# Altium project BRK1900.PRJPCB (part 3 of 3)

## Sheet Ethernet.SchDoc: BRK1900 - Ethernet
size C; Organization: Opal Kelly; Address1: 13500 SW 72nd Ave STE 100; Address2: Portland, OR  97223; Address3: 217.391.3724; Address4: http://www.opalkelly.com; DocumentNumber: 8; Revision: 1; SheetNumber: 8; SheetTotal: 11; PageSetup: Record=PageOptions¦CenterHorizontal=True¦CenterVertical=True¦PrintScale=0.52¦XCorrection=1.00¦YCorrection=1.00¦PrintKind=0¦BorderSize=5000000¦LeftOffset=0¦BottomOffset=0¦Orientation=2¦PaperLength=1000¦PaperWidth=1000¦Scale=100¦PaperSource=7¦PrintQuality=-4¦MediaType=1¦DitherType=10¦PaperKind=Letter¦PrintScaleMode=1
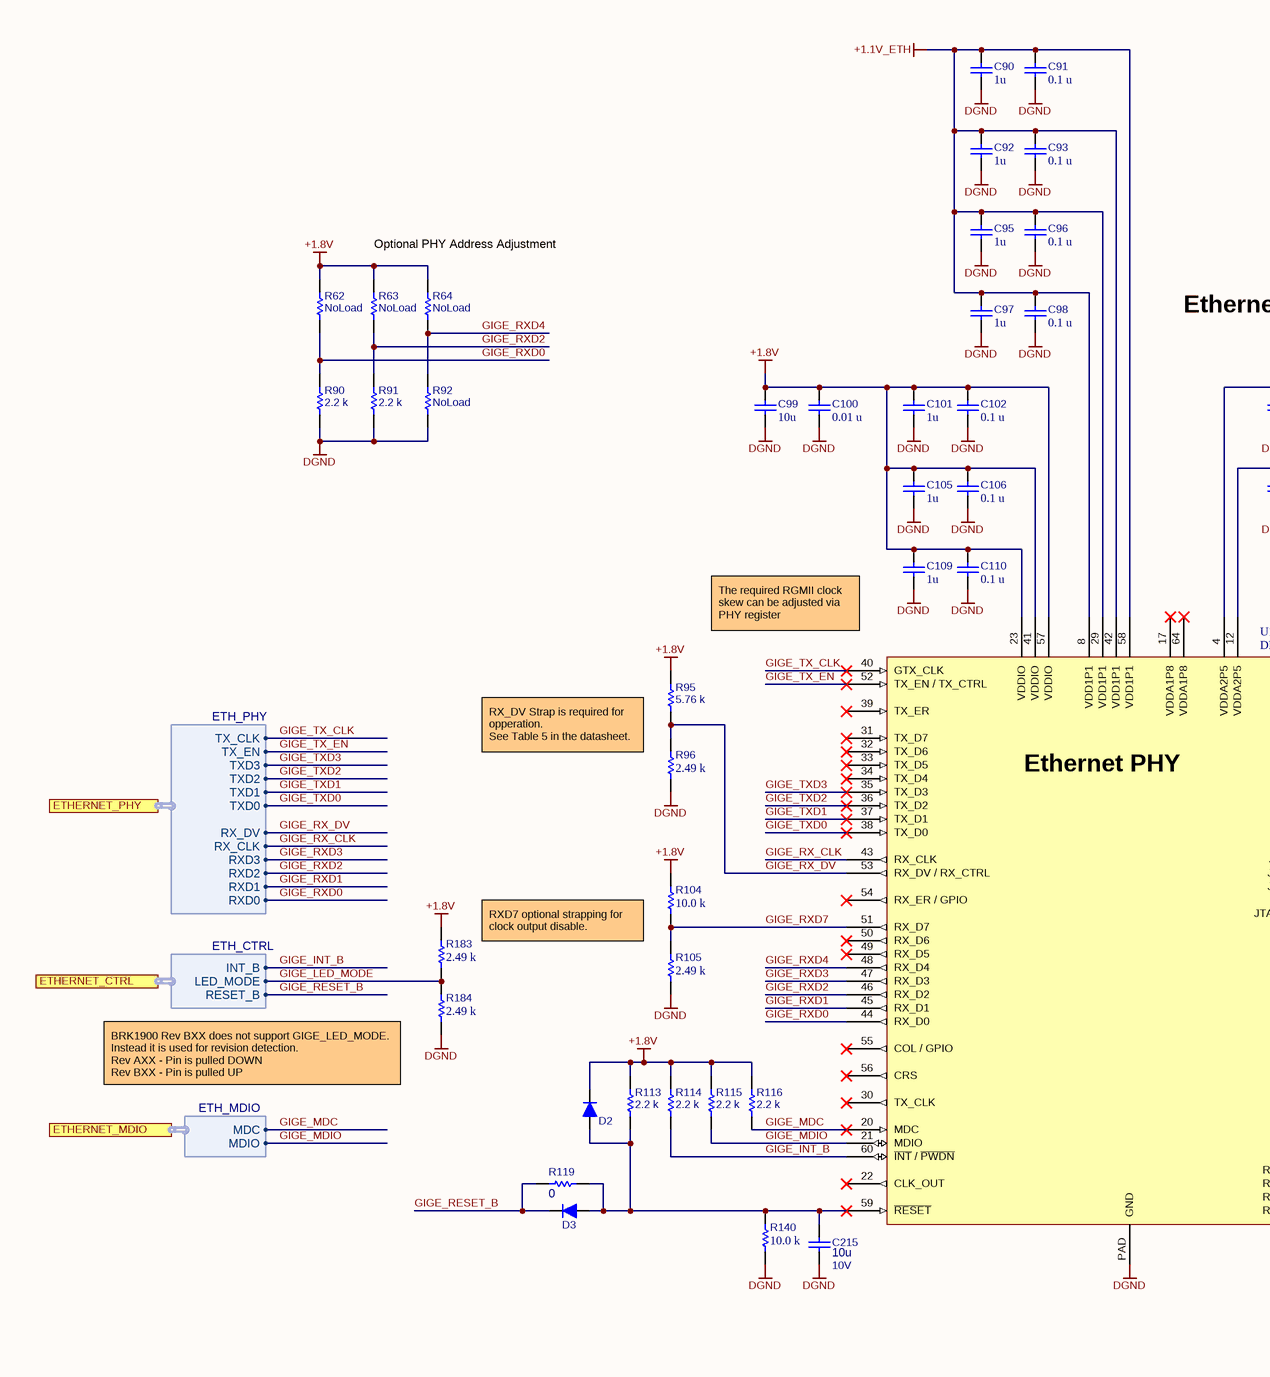
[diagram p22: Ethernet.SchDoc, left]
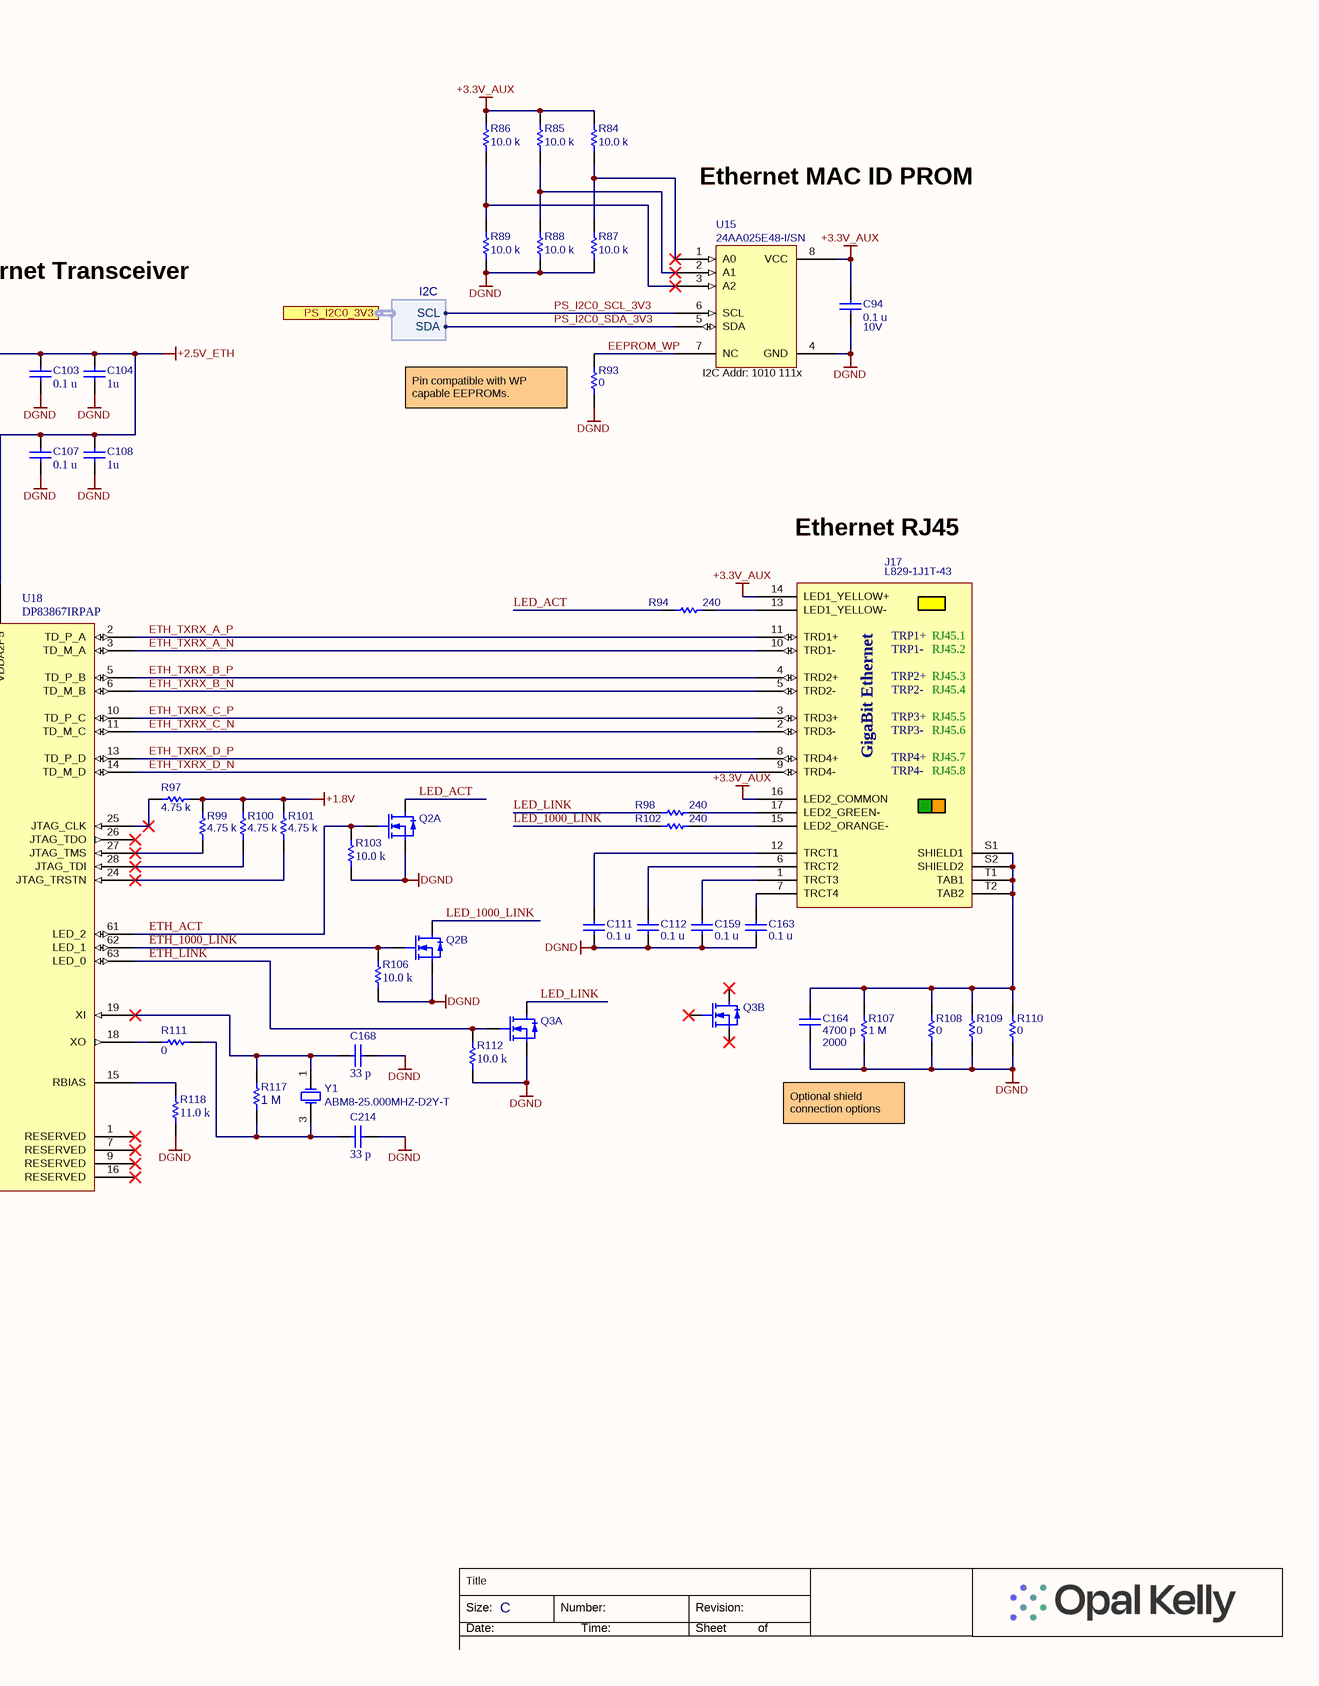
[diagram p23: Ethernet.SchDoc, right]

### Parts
C90  value 1u  [CAPC1005X06A]  (hidden comment: LMK105BJ105KV-F)
C91  value 0.1 u  [CAPC1005X06A]  (hidden comment: C0402C104K8PACTU)
C92  value 1u  [CAPC1005X06A]  (hidden comment: LMK105BJ105KV-F)
C93  value 0.1 u  [CAPC1005X06A]  (hidden comment: C0402C104K8PACTU)
C94  value 0.1 u  Voltage: 10V  [CAPC1005X06A]  (hidden comment: C0402C104K8PACTU)
C95  value 1u  [CAPC1005X06A]  (hidden comment: LMK105BJ105KV-F)
C96  value 0.1 u  [CAPC1005X06A]  (hidden comment: C0402C104K8PACTU)
C97  value 1u  [CAPC1005X06A]  (hidden comment: LMK105BJ105KV-F)
C98  value 0.1 u  [CAPC1005X06A]  (hidden comment: C0402C104K8PACTU)
C99  value 10u  [CAPC2012X14N]  (hidden comment: EMK212BJ106KG-T)
C100  value 0.01 u  [CAPC1005X06A]  (hidden comment: C0402C103K4RACTU)
C101  value 1u  [CAPC1005X06A]  (hidden comment: LMK105BJ105KV-F)
C102  value 0.1 u  [CAPC1005X06A]  (hidden comment: C0402C104K8PACTU)
C103  value 0.1 u  [CAPC1005X06A]  (hidden comment: C0402C104K8PACTU)
C104  value 1u  [CAPC1005X06A]  (hidden comment: LMK105BJ105KV-F)
C105  value 1u  [CAPC1005X06A]  (hidden comment: LMK105BJ105KV-F)
C106  value 0.1 u  [CAPC1005X06A]  (hidden comment: C0402C104K8PACTU)
C107  value 0.1 u  [CAPC1005X06A]  (hidden comment: C0402C104K8PACTU)
C108  value 1u  [CAPC1005X06A]  (hidden comment: LMK105BJ105KV-F)
C109  value 1u  [CAPC1005X06A]  (hidden comment: LMK105BJ105KV-F)
C110  value 0.1 u  [CAPC1005X06A]  (hidden comment: C0402C104K8PACTU)
C111  value 0.1 u  [CAPC1005X06A]  (hidden comment: TMK105BJ104KV-F)
C112  value 0.1 u  [CAPC1005X06A]  (hidden comment: TMK105BJ104KV-F)
C159  value 0.1 u  [CAPC1005X06A]  (hidden comment: TMK105BJ104KV-F)
C163  value 0.1 u  [CAPC1005X06A]  (hidden comment: TMK105BJ104KV-F)
C164  value 4700 p  Voltage: 2000  [CC4532-1812]  (hidden comment: GR443DR73D472KW01L)
C168  value 33 p  [CAPC1005X06A]  (hidden comment: C0402C330J5GACTU)
C214  value 33 p  [CAPC1005X06A]  (hidden comment: C0402C330J5GACTU)
C215  value 10u  Voltage: 10V  [CAPC2012X14N]  (hidden comment: LMK212BJ106KG-T)
D2  Diode  [SOD-123]  (value not drawn)
D3  Diode  [SOD-123]  (value not drawn)
J17  L829-1J1T-43  [L829-1J1T-43]
Q2  SI1922EDH-T1-GE3  [SOT363-6N]  (value not drawn)  (parts A,B of 2)
Q3  SI1922EDH-T1-GE3  [SOT363-6N]  (value not drawn)  (parts A,B of 2)
R62  NoLoad  [RESC1005X06A]
R63  NoLoad  [RESC1005X06A]
R64  NoLoad  [RESC1005X06A]
R84  value 10.0 k  [RESC1005X06A]  (hidden comment: CRCW040210K0FKED)
R85  value 10.0 k  [RESC1005X06A]  (hidden comment: CRCW040210K0FKED)
R86  value 10.0 k  [RESC1005X06A]  (hidden comment: CRCW040210K0FKED)
R87  value 10.0 k  [RESC1005X06A]  (hidden comment: CRCW040210K0FKED)
R88  value 10.0 k  [RESC1005X06A]  (hidden comment: CRCW040210K0FKED)
R89  value 10.0 k  [RESC1005X06A]  (hidden comment: CRCW040210K0FKED)
R90  value 2.2 k  [RESC1005X06A]  (hidden comment: CRCW04022K20JNED)
R91  value 2.2 k  [RESC1005X06A]  (hidden comment: CRCW04022K20JNED)
R92  NoLoad  [RESC1005X06A]
R93  value 0  [RESC1005X06A]  (hidden comment: CRCW04020000Z0ED)
R94  value 240  [RESC1005X06A]  (hidden comment: CRCW0402240RFKED)
R95  value 5.76 k  [RESC1005X06A]  (hidden comment: CRCW04025K76FKEDC)
R96  value 2.49 k  [RESC1005X06A]  (hidden comment: CRCW04022K49FKED)
R97  value 4.75 k  [RESC1005X06A]  (hidden comment: CRCW04024K75FKED)
R98  value 240  [RESC1005X06A]  (hidden comment: CRCW0402240RFKED)
R99  value 4.75 k  [RESC1005X06A]  (hidden comment: CRCW04024K75FKED)
R100  value 4.75 k  [RESC1005X06A]  (hidden comment: CRCW04024K75FKED)
R101  value 4.75 k  [RESC1005X06A]  (hidden comment: CRCW04024K75FKED)
R102  value 240  [RESC1005X06A]  (hidden comment: CRCW0402240RFKED)
R103  value 10.0 k  [RESC1005X06A]  (hidden comment: CRCW040210K0FKED)
R104  value 10.0 k  [RESC1005X06A]  (hidden comment: CRCW040210K0FKED)
R105  value 2.49 k  [RESC1005X06A]  (hidden comment: CRCW04022K49FKED)
R106  value 10.0 k  [RESC1005X06A]  (hidden comment: CRCW040210K0FKED)
R107  value 1 M  [RESC1005X06A]  (hidden comment: CRCW04021M00JNED)
R108  value 0  [RESC1005X06A]  (hidden comment: CRCW04020000Z0ED)
R109  value 0  [RESC1005X06A]  (hidden comment: CRCW04020000Z0ED)
R110  value 0  [RESC1005X06A]  (hidden comment: CRCW04020000Z0ED)
R111  value 0  [RESC1005X06A]  (hidden comment: CRCW04020000Z0ED)
R112  value 10.0 k  [RESC1005X06A]  (hidden comment: CRCW040210K0FKED)
R113  value 2.2 k  [RESC1005X06A]  (hidden comment: CRCW04022K20JNED)
R114  value 2.2 k  [RESC1005X06A]  (hidden comment: CRCW04022K20JNED)
R115  value 2.2 k  [RESC1005X06A]  (hidden comment: CRCW04022K20JNED)
R116  value 2.2 k  [RESC1005X06A]  (hidden comment: CRCW04022K20JNED)
R117  value 1 M  [RESC1005X06A]  (hidden comment: CRCW04021M00JNED)
R118  value 11.0 k  [RESC1005X06A]  (hidden comment: CRCW040211K0FKED)
R119  value 0  [RESC1005X06A]  (hidden comment: CRCW04020000Z0ED)
R140  value 10.0 k  [RESC1005X06A]  (hidden comment: CRCW040210K0FKED)
R183  value 2.49 k  [RESC1005X06A]  (hidden comment: CRCW04022K49FKED)
R184  value 2.49 k  [RESC1005X06A]  (hidden comment: CRCW04022K49FKED)
U15  24AA025E48-I/SN  [SO-G8]
U18  DP83867IRPAP  [DP83867IRPAP]
Y1  ABM8-25.000MHZ-D2Y-T  [OSC_SMD_32x25]

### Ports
ETHERNET_CTRL (harness ETH_CTRL), ETHERNET_MDIO (harness ETH_MDIO), ETHERNET_PHY (harness ETH_PHY), PS_I2C0_3V3 (harness I2C)

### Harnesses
ETH_PHY: TX_CLK, TX_EN, TXD3, TXD2, TXD1, TXD0, RX_DV, RX_CLK, RXD3, RXD2, RXD1, RXD0
ETH_MDIO: MDC, MDIO
ETH_CTRL: INT_B, LED_MODE, RESET_B
I2C: SCL, SDA

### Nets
+1.1V_ETH: C90.2 C91.2 C92.2 C93.2 C95.2 C96.2 C97.2 C98.2 U18.8(VDD1P1) U18.29(VDD1P1) U18.42(VDD1P1) U18.58(VDD1P1)
+1.8V: C99.2 C100.2 C101.2 C102.2 C105.2 C106.2 C109.2 C110.2 D2.2(K) R62.2 R63.2 R64.2 R95.2 R97.1 R99.2 R100.2 R101.2 R104.2 R113.2 R114.2 R115.2 R116.2 R183.2 U18.23(VDDIO) U18.41(VDDIO) U18.57(VDDIO)
+2.5V_ETH: C103.2 C104.2 C107.2 C108.2 U18.4(VDDA2P5) U18.12(VDDA2P5)
+3.3V_AUX: C94.2 J17.14(LED1_YELLOW+) J17.16(LED2_COMMON) R84.2 R85.2 R86.2 U15.8(VCC)
DGND: C90.1 C91.1 C92.1 C93.1 C94.1 C95.1 C96.1 C97.1 C98.1 C99.1 C100.1 C101.1 C102.1 C103.1 C104.1 C105.1 C106.1 C107.1 C108.1 C109.1 C110.1 C111.1 C112.1 C159.1 C163.1 C164.1 C168.2 C214.2 C215.1 Q2.1(S1) Q2.4(S2) Q3.1(S1) R87.1 R88.1 R89.1 R90.1 R91.1 R92.1 R93.1 R96.1 R103.1 R105.1 R106.1 R107.1 R108.1 R109.1 R110.1 R112.1 R118.1 R140.1 R184.1 U15.4(GND) U18.PAD(GND)
EEPROM_WP: R93.2 U15.7(NC)
ETH_1000_LINK: Q2.5(G2) R106.2 U18.62(LED_1)
ETH_ACT: Q2.2(G1) R103.2 U18.61(LED_2)
ETH_LINK: Q3.2(G1) R112.2 U18.63(LED_0)
ETH_TXRX_A_N: J17.10(TRD1-) U18.3(TD_M_A)
ETH_TXRX_A_P: J17.11(TRD1+) U18.2(TD_P_A)
ETH_TXRX_B_N: J17.5(TRD2-) U18.6(TD_M_B)
ETH_TXRX_B_P: J17.4(TRD2+) U18.5(TD_P_B)
ETH_TXRX_C_N: J17.2(TRD3-) U18.11(TD_M_C)
ETH_TXRX_C_P: J17.3(TRD3+) U18.10(TD_P_C)
ETH_TXRX_D_N: J17.9(TRD4-) U18.14(TD_M_D)
ETH_TXRX_D_P: J17.8(TRD4+) U18.13(TD_P_D)
GIGE_INT_B: R114.1 U18.60(~{INT}_/_~{PWDN}) ; port ETHERNET_CTRL.INT_B
GIGE_LED_MODE: R183.1 R184.2 ; port ETHERNET_CTRL.LED_MODE
GIGE_MDC: R116.1 U18.20(MDC) ; port ETHERNET_MDIO.MDC
GIGE_MDIO: R115.1 U18.21(MDIO) ; port ETHERNET_MDIO.MDIO
GIGE_RESET_B: D3.2(K) R119.1 ; port ETHERNET_CTRL.RESET_B
GIGE_RX_CLK: U18.43(RX_CLK) ; port ETHERNET_PHY.RX_CLK
GIGE_RX_DV: R95.1 R96.2 U18.53(RX_DV_/_RX_CTRL) ; port ETHERNET_PHY.RX_DV
GIGE_RXD0: R62.1 R90.2 U18.44(RX_D0) ; port ETHERNET_PHY.RXD0
GIGE_RXD1: U18.45(RX_D1) ; port ETHERNET_PHY.RXD1
GIGE_RXD2: R63.1 R91.2 U18.46(RX_D2) ; port ETHERNET_PHY.RXD2
GIGE_RXD3: U18.47(RX_D3) ; port ETHERNET_PHY.RXD3
GIGE_RXD4: R64.1 R92.2 U18.48(RX_D4)
GIGE_RXD7: R104.1 R105.2 U18.51(RX_D7)
GIGE_TX_CLK: U18.40(GTX_CLK) ; port ETHERNET_PHY.TX_CLK
GIGE_TX_EN: U18.52(TX_EN_/_TX_CTRL) ; port ETHERNET_PHY.TX_EN
GIGE_TXD0: U18.38(TX_D0) ; port ETHERNET_PHY.TXD0
GIGE_TXD1: U18.37(TX_D1) ; port ETHERNET_PHY.TXD1
GIGE_TXD2: U18.36(TX_D2) ; port ETHERNET_PHY.TXD2
GIGE_TXD3: U18.35(TX_D3) ; port ETHERNET_PHY.TXD3
LED_1000_LINK: Q2.3(D2) R102.2
LED_ACT: Q2.6(D1) R94.2
LED_LINK: Q3.6(D1) R98.2
PS_I2C0_SCL_3V3: U15.6(SCL) ; port PS_I2C0_3V3.SCL
PS_I2C0_SDA_3V3: U15.5(SDA) ; port PS_I2C0_3V3.SDA
NetC111_2: C111.2 J17.12(TRCT1)
NetC112_2: C112.2 J17.6(TRCT2)
NetC159_2: C159.2 J17.1(TRCT3)
NetC163_2: C163.2 J17.7(TRCT4)
NetC164_2: C164.2 J17.S1(SHIELD1) J17.S2(SHIELD2) J17.T1(TAB1) J17.T2(TAB2) R107.2 R108.2 R109.2 R110.2
NetC168_1: C168.1 R117.2 U18.19(XI) Y1.1(OSC1)
NetC214_1: C214.1 R111.2 R117.1 Y1.3(OSC2)
NetC215_2: C215.2 D2.1(A) D3.1(A) R113.1 R119.2 R140.2 U18.59(~{RESET})
NetJ17_13: J17.13(LED1_YELLOW-) R94.1
NetJ17_15: J17.15(LED2_ORANGE-) R102.1
NetJ17_17: J17.17(LED2_GREEN-) R98.1
NetR84_1: R84.1 R87.2 U15.1(A0)
NetR85_1: R85.1 R88.2 U15.2(A1)
NetR86_1: R86.1 R89.2 U15.3(A2)
NetR97_2: R97.2 U18.25(JTAG_CLK)
NetR99_1: R99.1 U18.27(JTAG_TMS)
NetR100_1: R100.1 U18.28(JTAG_TDI)
NetR101_1: R101.1 U18.24(JTAG_TRSTN)
NetR111_1: R111.1 U18.18(XO)
NetR118_2: R118.2 U18.15(RBIAS)

Not connected (* = marked no-connect by the designer): Q3 3(D2)* 4(S2)* 5(G2)*; U18 1(RESERVED)* 7(RESERVED)* 9(RESERVED)* 16(RESERVED)* 17(VDDA1P8)* 22(CLK_OUT)* 26(JTAG_TDO)* 30(TX_CLK)* 31(TX_D7)* 32(TX_D6)* 33(TX_D5)* 34(TX_D4)* 39(TX_ER)* 49(RX_D5)* 50(RX_D6)* 54(RX_ER_/_GPIO)* 55(COL_/_GPIO)* 56(CRS)* 64(VDDA1P8)*

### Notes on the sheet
- Optional PHY Address Adjustment
- Ethernet MAC ID PROM
- Ethernet Transceiver
- (near R93) Pin compatible with WP capable EEPROMs.
- (near U15) I2C Addr: 1010 111x
- Ethernet RJ45
- The required RGMII clock skew can be adjusted via PHY register
- RX_DV Strap is required for opperation.
  See Table 5 in the datasheet.
- (near U18) Ethernet PHY
- RXD7 optional strapping for clock output disable.
- (near R184) BRK1900 Rev BXX does not support GIGE_LED_MODE. Instead it is used for revision detection.
  Rev AXX - Pin is pulled DOWN
  Rev BXX - Pin is pulled UP
- Optional shield connection options
- Title
- Size:
- Date:
- C
- Number:
- Time:
- Revision:
- Sheet
- of

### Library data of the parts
C90 C92 C95 C97 C101 C104 C105 C108 C109 = 000480: Ceramic capacitor; Partnumber: 000480; Manufacturer: Taiyo Yuden; ValueFloat: 1E-6; Tolerance (%): 10; Description 2: SM-0402, 10%, 10v
C91 C93 C96 C98 C102 C103 C106 C107 C110 = 000070: Ceramic capacitor; Partnumber: 000070; Manufacturer: Kemet; ValueFloat: 1E-7; Tolerance (%): 10; Description 2: SM-0402, 10%, 10v
C94 = 000070: Ceramic capacitor; Manufacturer: Kemet; partnumber: 000070; ValueFloat: 1E-7; x_tolerance: 10
C99 = 001786: Ceramic capacitor; Partnumber: 001786; Manufacturer: Taiyo Yuden; ValueFloat: 1E-5; Tolerance (%): 10; Description 2: SM-0805, 10%, 16V
C100 = 000295: Ceramic Capacitor; Partnumber: 000295; Manufacturer: Kemet; ValueFloat: 1E-8; Tolerance (%): 10; Description 2: SM-0402, 10%, 16V, X5R
C111 C112 C159 C163 = 001073: Ceramic capacitor; Partnumber: 001073; Manufacturer: Taiyo Yuden; ValueFloat: 1E-7; Tolerance (%): 10; Description 2: 0402, 25V
C164 = 002158: Ceramic capacitor High Voltage; Partnumber: 002158; Manufacturer: Murata; ValueFloat: 4.7E-9; Tolerance (%): 10; Description 2: SM-1812, 10%, 2000V
C168 C214 = 000935: Ceramic capacitor; Partnumber: 000935; Manufacturer: Kemet; ValueFloat: 3.3E-11; Tolerance (%): 5; Voltage: 50; Description 2: SM-0402, 5%, 50v
C215 = 000491: Ceramic capacitor; Manufacturer: Taiyo Yuden; partnumber: 000491; ValueFloat: 1E-5; x_tolerance: 10
D2 D3 = 001302: Default Diode; Manufacturer: Micro Commercial Co; PartNumber: 001302; manufacturer_pn: 1N4148W-TP; Class I: Discrete; Class II: Diode - Switching
J17 = 001517: RJ-45; Manufacturer: Bel Fuse, Inc.; partnumber: 001517
Q2 Q3 = 002018: Partnumber: 002018; manufacturer: Vishay
R62-R64 R92 = 002438: NoLoad resistor; Partnumber: 002438; Manufacturer: Generic
R84-R89 = 001521: Thick-film resistor; Manufacturer: Vishay; partnumber: 001521; ValueFloat: 10000; x_tolerance: 1
R90 R91 R113-R116 = 000801: Thick-film resistor; Partnumber: 000801; Manufacturer: Vishay; ValueFloat: 2200; Tolerance (%): 5; Description 2: SM-0402, 5%, 1/16W
R93 R108-R111 = 000755: Thick-film resistor; Manufacturer: Vishay; partnumber: 000755; Description 2: SM-0402, 1%, 1/16W; Tolerance (%): 1
R94 R98 R102 = 000760: Thick-film resistor; Manufacturer: Vishay; partnumber: 000760; x_tolerance: 1
R95 = 002155: Thick-film resistor; Partnumber: 002155; Manufacturer: Vishay; ValueFloat: 5760; Tolerance (%): 1; Description 2: SM-0402, 1%, 1/16W
R96 R105 R183 R184 = 001388: Thick-film resistor; Partnumber: 001388; Manufacturer: Vishay; ValueFloat: 2490; Tolerance (%): 1; Description 2: SM-0402, 1%, 1/16W
R97 R99-R101 = 001008: Partnumber: 001008; manufacturer: Vishay; ValueFloat: 4750; x_tolerance: 1
R103 R104 R106 R112 R140 = 001521: Thick-film resistor; Partnumber: 001521; Manufacturer: Vishay; ValueFloat: 10000; Tolerance (%): 1; Description 2: SM-0402, 1%, 1/16W
R107 = 000800: Thick-film resistor; Partnumber: 000800; Manufacturer: Vishay; ValueFloat: 1000000; Tolerance (%): 5; Description 2: SM-0402, 5%, 1/16W
R117 = 000800: Thick-film resistor; Manufacturer: Vishay; partnumber: 000800; ValueFloat: 1000000; x_tolerance: 5
R118 = 001840: Thick-film resistor; Partnumber: 001840; Manufacturer: Vishay; ValueFloat: 11000; Tolerance (%): 1; Description 2: SM-0402, 1%, 1/16W
R119 = 000755: Thick-film resistor; Manufacturer: Vishay; partnumber: 000755; x_tolerance: 1
U15 = 001296: 2 kb I2C EEPROM, 400 kHz; Manufacturer: Microchip; partnumber: 001296
U18 = 002091: Gigabit ethernet transceiver, RGMII; Partnumber: 002091; Manufacturer: Texas Instruments
Y1 = 001531: Crystal; Manufacturer: Abracon; partnumber: 001531

## Sheet Clocks.SchDoc: BRK1900 - Clocks
size C; Organization: Opal Kelly; Address1: 13500 SW 72nd Ave STE 100; Address2: Portland, OR  97223; Address3: 217.391.3724; Address4: http://www.opalkelly.com; DocumentNumber: 9; Revision: 1; SheetNumber: 9; SheetTotal: 11; PageSetup: Record=PageOptions¦CenterHorizontal=True¦CenterVertical=True¦PrintScale=0.52¦XCorrection=1.00¦YCorrection=1.00¦PrintKind=0¦BorderSize=5000000¦LeftOffset=0¦BottomOffset=0¦Orientation=2¦PaperLength=1000¦PaperWidth=1000¦Scale=100¦PaperSource=7¦PrintQuality=-4¦MediaType=1¦DitherType=10¦PaperKind=Letter¦PrintScaleMode=1
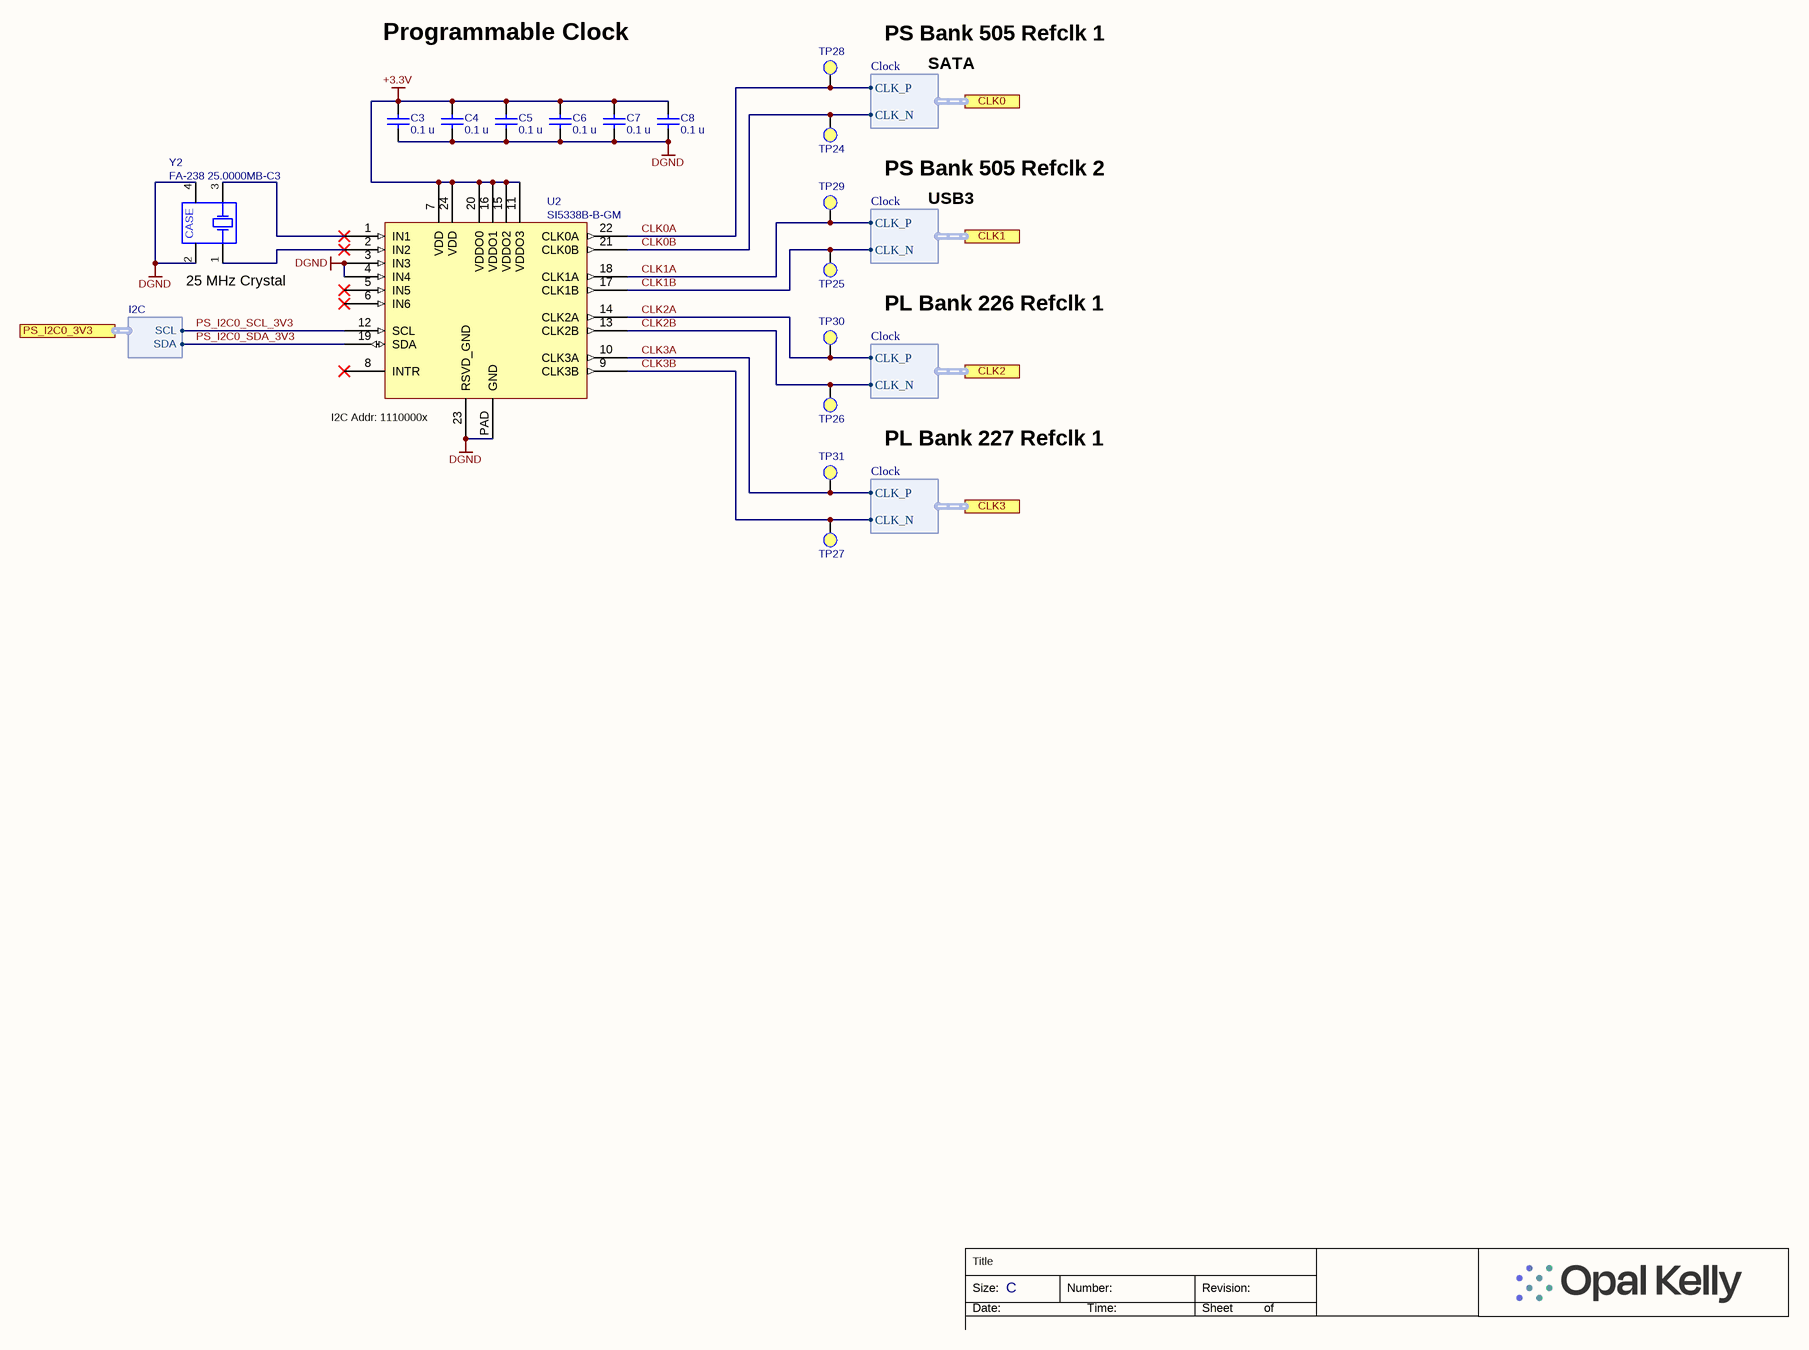
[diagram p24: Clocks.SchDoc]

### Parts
C3  value 0.1 u  [CAPC1005X06A]  (hidden comment: C0402C104K8PACTU)
C4  value 0.1 u  [CAPC1005X06A]  (hidden comment: C0402C104K8PACTU)
C5  value 0.1 u  [CAPC1005X06A]  (hidden comment: C0402C104K8PACTU)
C6  value 0.1 u  [CAPC1005X06A]  (hidden comment: C0402C104K8PACTU)
C7  value 0.1 u  [CAPC1005X06A]  (hidden comment: C0402C104K8PACTU)
C8  value 0.1 u  [CAPC1005X06A]  (hidden comment: C0402C104K8PACTU)
TP24  TESTPOINT-SMD20  [TP-SMD20]  (value not drawn)
TP25  TESTPOINT-SMD20  [TP-SMD20]  (value not drawn)
TP26  TESTPOINT-SMD20  [TP-SMD20]  (value not drawn)
TP27  TESTPOINT-SMD20  [TP-SMD20]  (value not drawn)
TP28  TESTPOINT-SMD20  [TP-SMD20]  (value not drawn)
TP29  TESTPOINT-SMD20  [TP-SMD20]  (value not drawn)
TP30  TESTPOINT-SMD20  [TP-SMD20]  (value not drawn)
TP31  TESTPOINT-SMD20  [TP-SMD20]  (value not drawn)
U2  SI5338B-B-GM  [Si5338]
Y2  FA-238 25.0000MB-C3  [OSC_SMD_32x25]

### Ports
CLK0 (harness Clock), CLK1 (harness Clock), CLK2 (harness Clock), CLK3 (harness Clock), PS_I2C0_3V3 (harness I2C)

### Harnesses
Clock: CLK_P, CLK_N
I2C: SCL, SDA

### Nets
+3.3V: C3.2 C4.2 C5.2 C6.2 C7.2 C8.2 U2.7(VDD) U2.11(VDDO3) U2.15(VDDO2) U2.16(VDDO1) U2.20(VDDO0) U2.24(VDD)
DGND: C3.1 C4.1 C5.1 C6.1 C7.1 C8.1 U2.3(IN3) U2.4(IN4) U2.23(RSVD_GND) U2.PAD(GND) Y2.2(CASE) Y2.4(CASE)
CLK0A: TP28.1(PIN) U2.22(CLK0A) ; port CLK0.CLK_P
CLK0B: TP24.1(PIN) U2.21(CLK0B) ; port CLK0.CLK_N
CLK1A: TP29.1(PIN) U2.18(CLK1A) ; port CLK1.CLK_P
CLK1B: TP25.1(PIN) U2.17(CLK1B) ; port CLK1.CLK_N
CLK2A: TP30.1(PIN) U2.14(CLK2A) ; port CLK2.CLK_P
CLK2B: TP26.1(PIN) U2.13(CLK2B) ; port CLK2.CLK_N
CLK3A: TP31.1(PIN) U2.10(CLK3A) ; port CLK3.CLK_P
CLK3B: TP27.1(PIN) U2.9(CLK3B) ; port CLK3.CLK_N
PS_I2C0_SCL_3V3: U2.12(SCL) ; port PS_I2C0_3V3.SCL
PS_I2C0_SDA_3V3: U2.19(SDA) ; port PS_I2C0_3V3.SDA
NetU2_1: U2.1(IN1) Y2.3(OSC2)
NetU2_2: U2.2(IN2) Y2.1(OSC1)

Not connected (* = marked no-connect by the designer): U2 5(IN5)* 6(IN6)* 8(INTR)*

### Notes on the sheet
- Programmable Clock
- PS Bank 505 Refclk 1
- SATA
- PS Bank 505 Refclk 2
- USB3
- (near Y2) 25 MHz Crystal
- PL Bank 226 Refclk 1
- (near U2) I2C Addr: 1110000x
- PL Bank 227 Refclk 1
- Title
- Size:
- Date:
- C
- Number:
- Time:
- Revision:
- Sheet
- of

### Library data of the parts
C3-C8 = 000070: Partnumber: 000070; manufacturer: Kemet; ValueFloat: 1E-7; x_tolerance: 10
TP24-TP31 = TESTPOINT-SMD20: Test point, surface-mount, 20mil; partnumber: ALIGNI_IGNORE
U2 = 001741: Partnumber: 001741; manufacturer: Silicon Labs
Y2 = 001742: Partnumber: 001742; manufacturer: Epson

## Sheet DisplayPort-Source.SchDoc: BRK1900 - DisplayPort Source
size C; Organization: Opal Kelly; Address1: 13500 SW 72nd Ave STE 100; Address2: Portland, OR  97223; Address3: 217.391.3724; Address4: http://www.opalkelly.com; DocumentNumber: 10; Revision: 1; SheetNumber: 10; SheetTotal: 11; PageSetup: Record=PageOptions¦CenterHorizontal=True¦CenterVertical=True¦PrintScale=0.52¦XCorrection=1.00¦YCorrection=1.00¦PrintKind=0¦BorderSize=5000000¦LeftOffset=0¦BottomOffset=0¦Orientation=2¦PaperLength=1000¦PaperWidth=1000¦Scale=100¦PaperSource=7¦PrintQuality=-4¦MediaType=1¦DitherType=10¦PaperKind=Letter¦PrintScaleMode=1
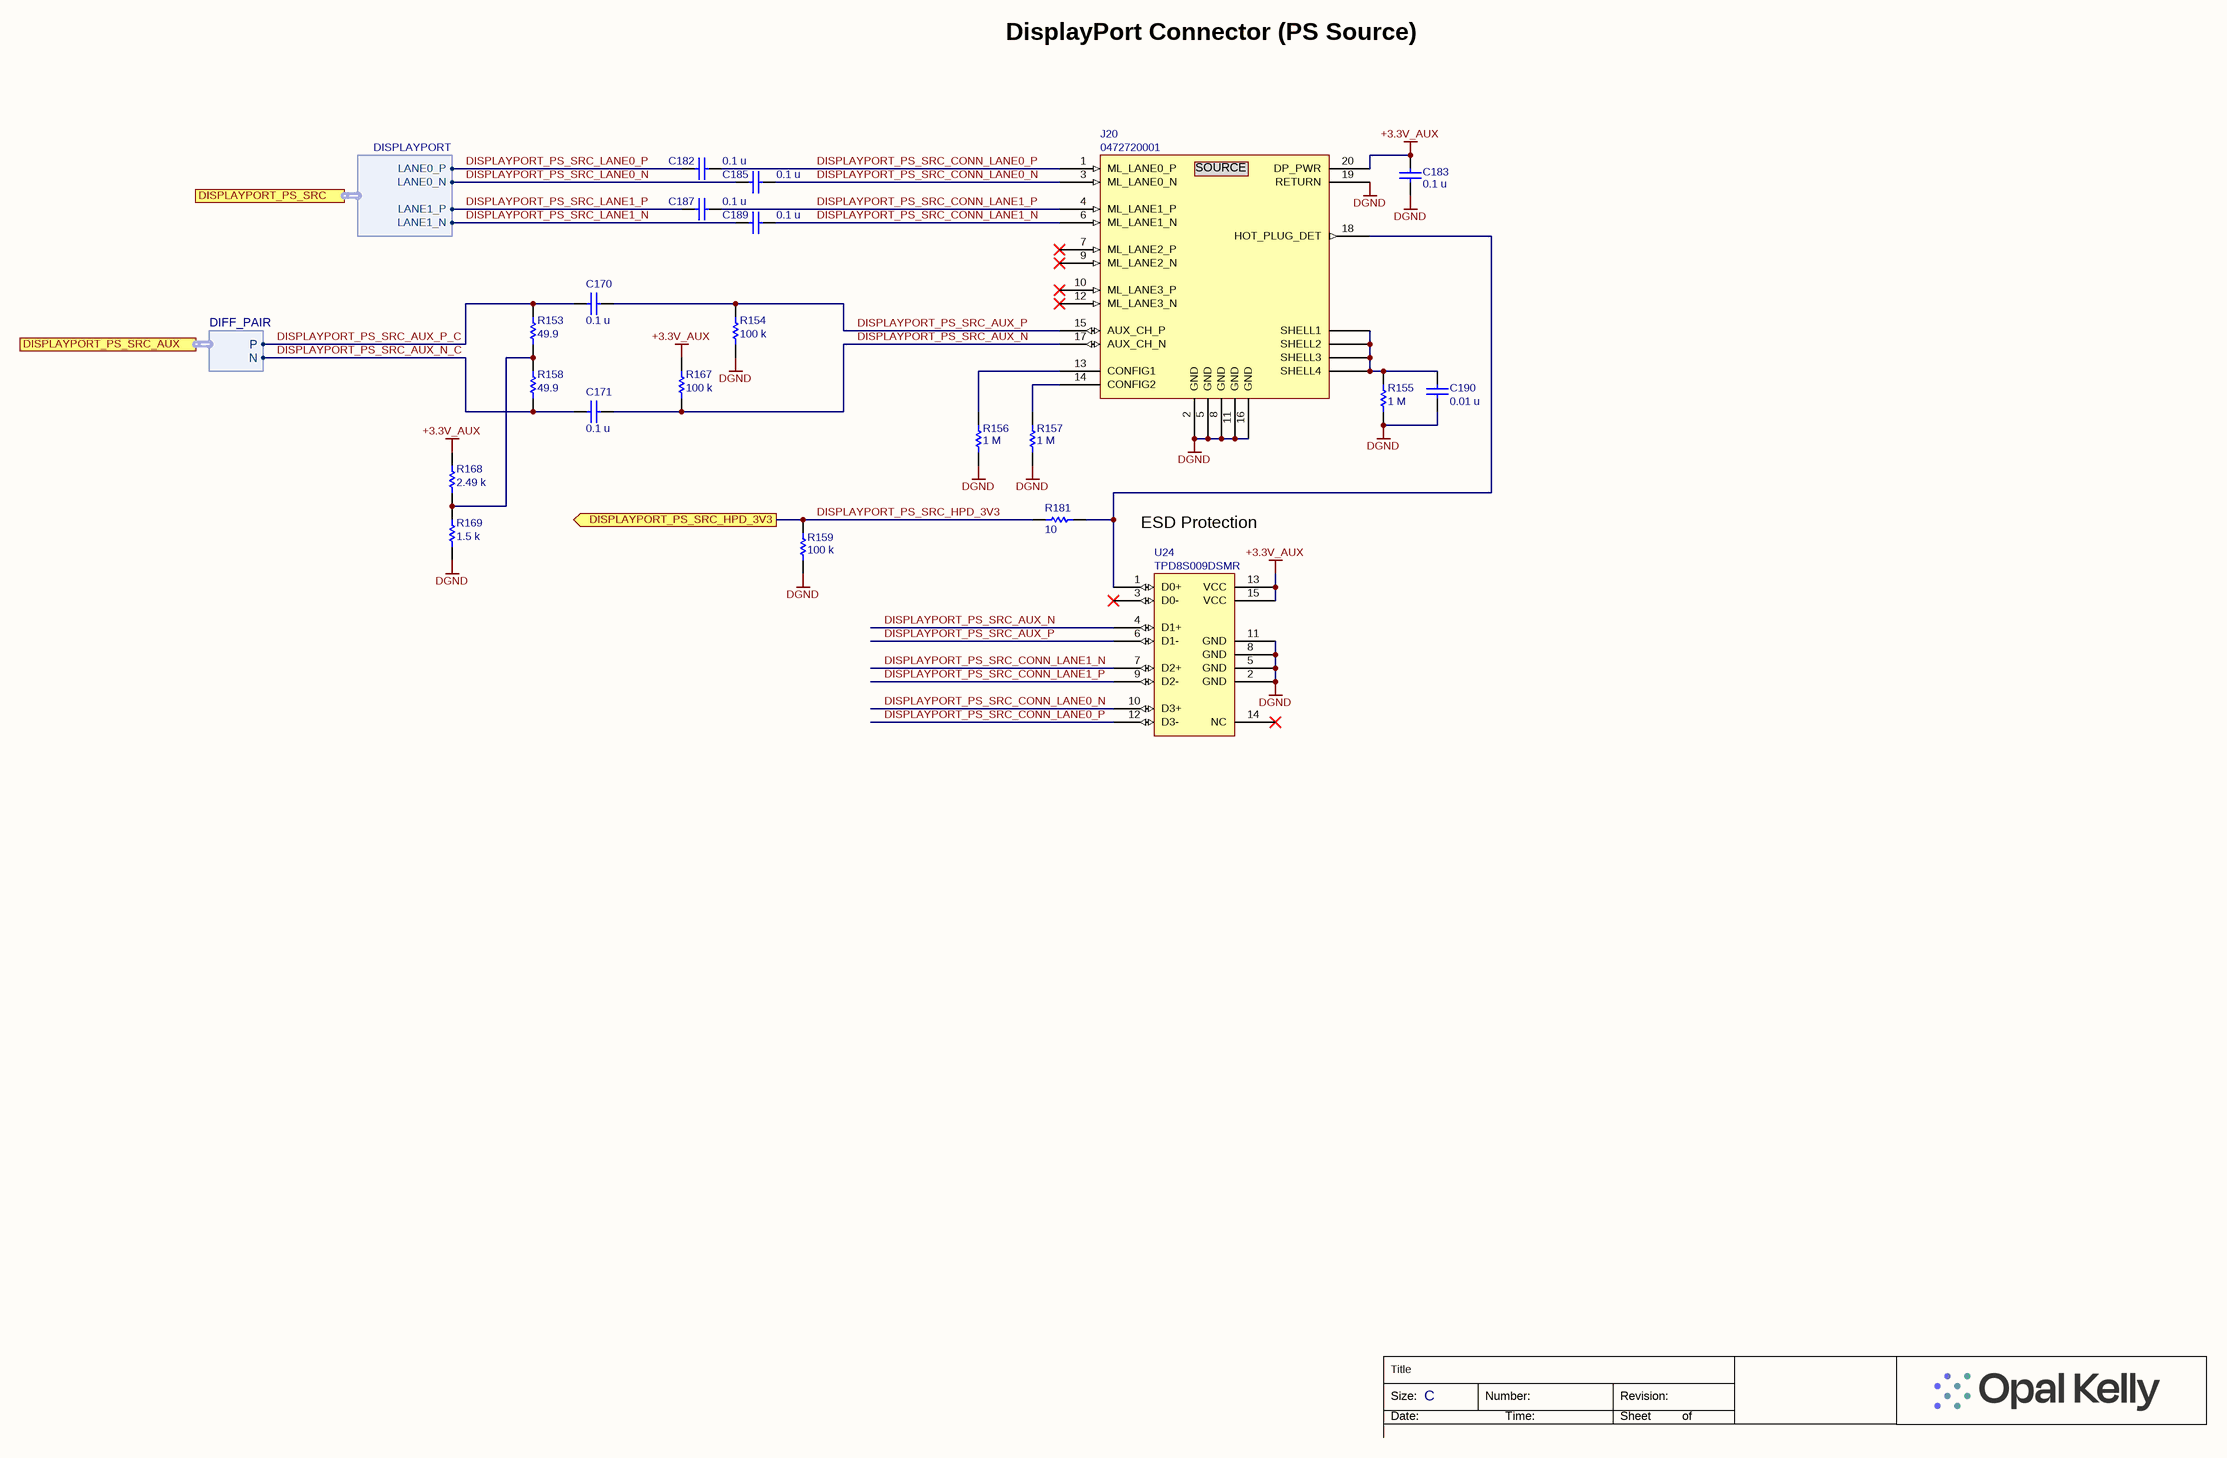
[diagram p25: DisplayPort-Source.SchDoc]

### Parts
C170  value 0.1 u  [CAPC1005X06A]  (hidden comment: SM-0402, 10%, 10v)
C171  value 0.1 u  [CAPC1005X06A]  (hidden comment: SM-0402, 10%, 10v)
C182  value 0.1 u  [CAPC1005X06A]  (hidden comment: SM-0402, 10%, 10v)
C183  value 0.1 u  [CAPC1005X06A]  (hidden comment: SM-0402, 10%, 10v)
C185  value 0.1 u  [CAPC1005X06A]  (hidden comment: SM-0402, 10%, 10v)
C187  value 0.1 u  [CAPC1005X06A]  (hidden comment: SM-0402, 10%, 10v)
C189  value 0.1 u  [CAPC1005X06A]  (hidden comment: SM-0402, 10%, 10v)
C190  value 0.01 u  [CAPC1005X06A]  (hidden comment: C0402C103K4RACTU)
J20  0472720001  [0472720001]
R153  value 49.9  [RESC1005X06A]  (hidden comment: CRCW040249R9FKEDC)
R154  value 100 k  [RESC1005X06A]  (hidden comment: CRCW0402100KFKED)
R155  value 1 M  [RESC1005X06A]  (hidden comment: CRCW04021M00FKEDC)
R156  value 1 M  [RESC1005X06A]  (hidden comment: CRCW04021M00FKEDC)
R157  value 1 M  [RESC1005X06A]  (hidden comment: CRCW04021M00FKEDC)
R158  value 49.9  [RESC1005X06A]  (hidden comment: CRCW040249R9FKEDC)
R159  value 100 k  [RESC1005X06A]  (hidden comment: CRCW0402100KFKED)
R167  value 100 k  [RESC1005X06A]  (hidden comment: CRCW0402100KFKED)
R168  value 2.49 k  [RESC1005X06A]  (hidden comment: CRCW04022K49FKED)
R169  value 1.5 k  [RESC1005X06A]  (hidden comment: CRCW04021K50FKED)
R181  value 10  [RESC1005X06A]  (hidden comment: CRCW040210R0FKED)
U24  TPD8S009DSMR  [TPD8S009DSMR]

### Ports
DISPLAYPORT_PS_SRC (harness DISPLAYPORT), DISPLAYPORT_PS_SRC_AUX (harness DIFF_PAIR), DISPLAYPORT_PS_SRC_HPD_3V3 (out)

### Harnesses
DISPLAYPORT: LANE0_P, LANE0_N, LANE1_P, LANE1_N
DIFF_PAIR: P, N

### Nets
+3.3V_AUX: C183.2 J20.20(DP_PWR) R167.2 R168.2 U24.13(VCC) U24.15(VCC)
DGND: C183.1 C190.1 J20.2(GND) J20.5(GND) J20.8(GND) J20.11(GND) J20.16(GND) J20.19(RETURN) R154.1 R155.1 R156.2 R157.2 R159.1 R169.1 U24.2(GND) U24.5(GND) U24.8(GND) U24.11(GND)
DISPLAYPORT_PS_SRC_AUX_N: C171.1 J20.17(AUX_CH_N) R167.1 U24.4(D1+)
DISPLAYPORT_PS_SRC_AUX_N_C: C171.2 R158.1 ; port DISPLAYPORT_PS_SRC_AUX.N
DISPLAYPORT_PS_SRC_AUX_P: C170.1 J20.15(AUX_CH_P) R154.2 U24.6(D1-)
DISPLAYPORT_PS_SRC_AUX_P_C: C170.2 R153.2 ; port DISPLAYPORT_PS_SRC_AUX.P
DISPLAYPORT_PS_SRC_CONN_LANE0_N: C185.1 J20.3(ML_LANE0_N) U24.10(D3+)
DISPLAYPORT_PS_SRC_CONN_LANE0_P: C182.1 J20.1(ML_LANE0_P) U24.12(D3-)
DISPLAYPORT_PS_SRC_CONN_LANE1_N: C189.1 J20.6(ML_LANE1_N) U24.7(D2+)
DISPLAYPORT_PS_SRC_CONN_LANE1_P: C187.1 J20.4(ML_LANE1_P) U24.9(D2-)
DISPLAYPORT_PS_SRC_HPD_3V3: R159.2 R181.1 ; port DISPLAYPORT_PS_SRC_HPD_3V3
DISPLAYPORT_PS_SRC_LANE0_N: C185.2 ; port DISPLAYPORT_PS_SRC.LANE0_N
DISPLAYPORT_PS_SRC_LANE0_P: C182.2 ; port DISPLAYPORT_PS_SRC.LANE0_P
DISPLAYPORT_PS_SRC_LANE1_N: C189.2 ; port DISPLAYPORT_PS_SRC.LANE1_N
DISPLAYPORT_PS_SRC_LANE1_P: C187.2 ; port DISPLAYPORT_PS_SRC.LANE1_P
NetC190_2: C190.2 J20.SHELL1 J20.SHELL2 J20.SHELL3 J20.SHELL4 R155.2
NetJ20_13: J20.13(CONFIG1) R156.1
NetJ20_14: J20.14(CONFIG2) R157.1
NetJ20_18: J20.18(HOT_PLUG_DET) R181.2 U24.1(D0+)
NetR153_1: R153.1 R158.2 R168.1 R169.2

Not connected (* = marked no-connect by the designer): J20 7(ML_LANE2_P)* 9(ML_LANE2_N)* 10(ML_LANE3_P)* 12(ML_LANE3_N)*; U24 3(D0-)* 14(NC)*

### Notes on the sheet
- DisplayPort Connector (PS Source)
- ESD Protection
- Title
- Size:
- Date:
- C
- Number:
- Time:
- Revision:
- Sheet
- of

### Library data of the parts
C170 C171 C182 C183 C185 C187 C189 = 000070: Partnumber: 000070; manufacturer: Kemet; manufacturer_pn: C0402C104K8PACTU; ValueFloat: 1E-7; id: 750; inventory_price: 0.0023; reorder_quantity: 70000; x_tolerance: 10
C190 = 000295: Partnumber: 000295; manufacturer: Kemet; ValueFloat: 1E-8; x_tolerance: 10
J20 = 001943: DisplayPort, full-size, right-angle; Partnumber: 001943; Manufacturer: Molex
R153 R158 = 001715: Partnumber: 001715; manufacturer: Vishay; x_tolerance: 1
R154 R159 R167 = 001070: Partnumber: 001070; manufacturer: Vishay; ValueFloat: 100000; x_tolerance: 1
R155-R157 = 001850: Partnumber: 001850; manufacturer: Vishay; ValueFloat: 1000000; x_tolerance: 5
R168 = 001388: Partnumber: 001388; manufacturer: Vishay; ValueFloat: 2490; x_tolerance: 1
R169 = 002012: Partnumber: 002012; manufacturer: Vishay; ValueFloat: 1500; x_tolerance: 1
R181 = 000969: Partnumber: 000969; manufacturer: Vishay; x_tolerance: 1
U24 = 001946: Partnumber: 001946; manufacturer: Texas Instruments

## Sheet JTAG.SchDoc: JTAG
size C; Author: Casey Smith; Organization: Opal Kelly; Address1: 13500 SW 72nd Ave STE 100; Address2: Portland, OR 97223; Address3: 217.391.3724; Address4: http://www.opalkelly.com; DocumentNumber: 11; Revision: 1; SheetNumber: 11; SheetTotal: 11
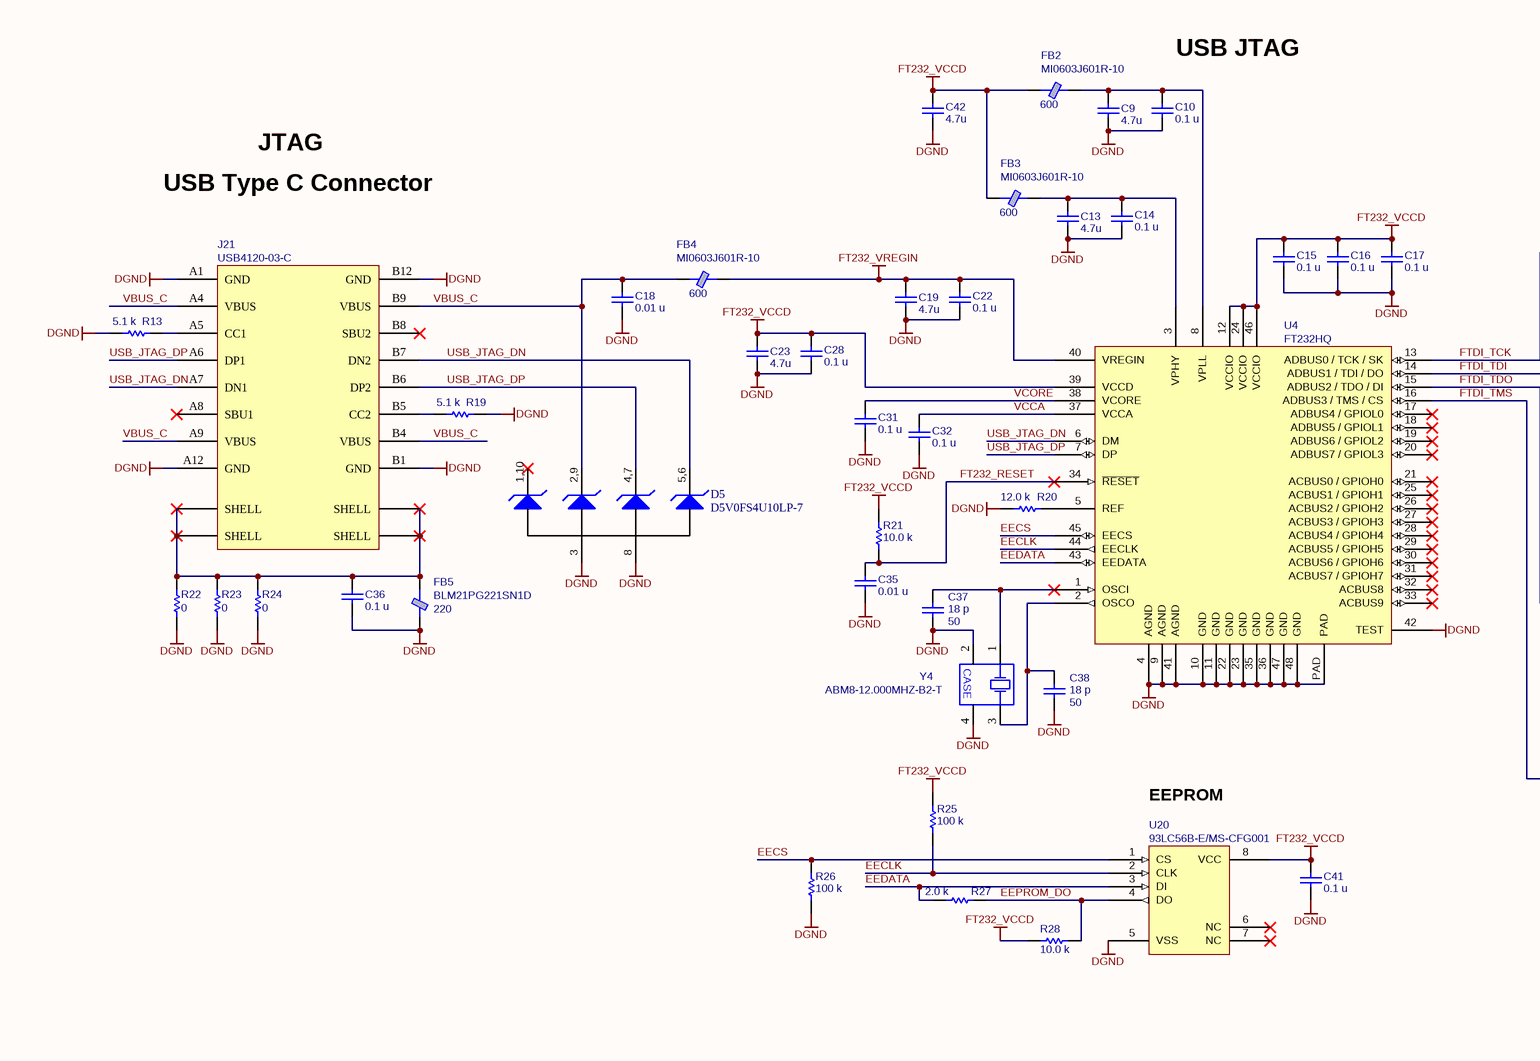
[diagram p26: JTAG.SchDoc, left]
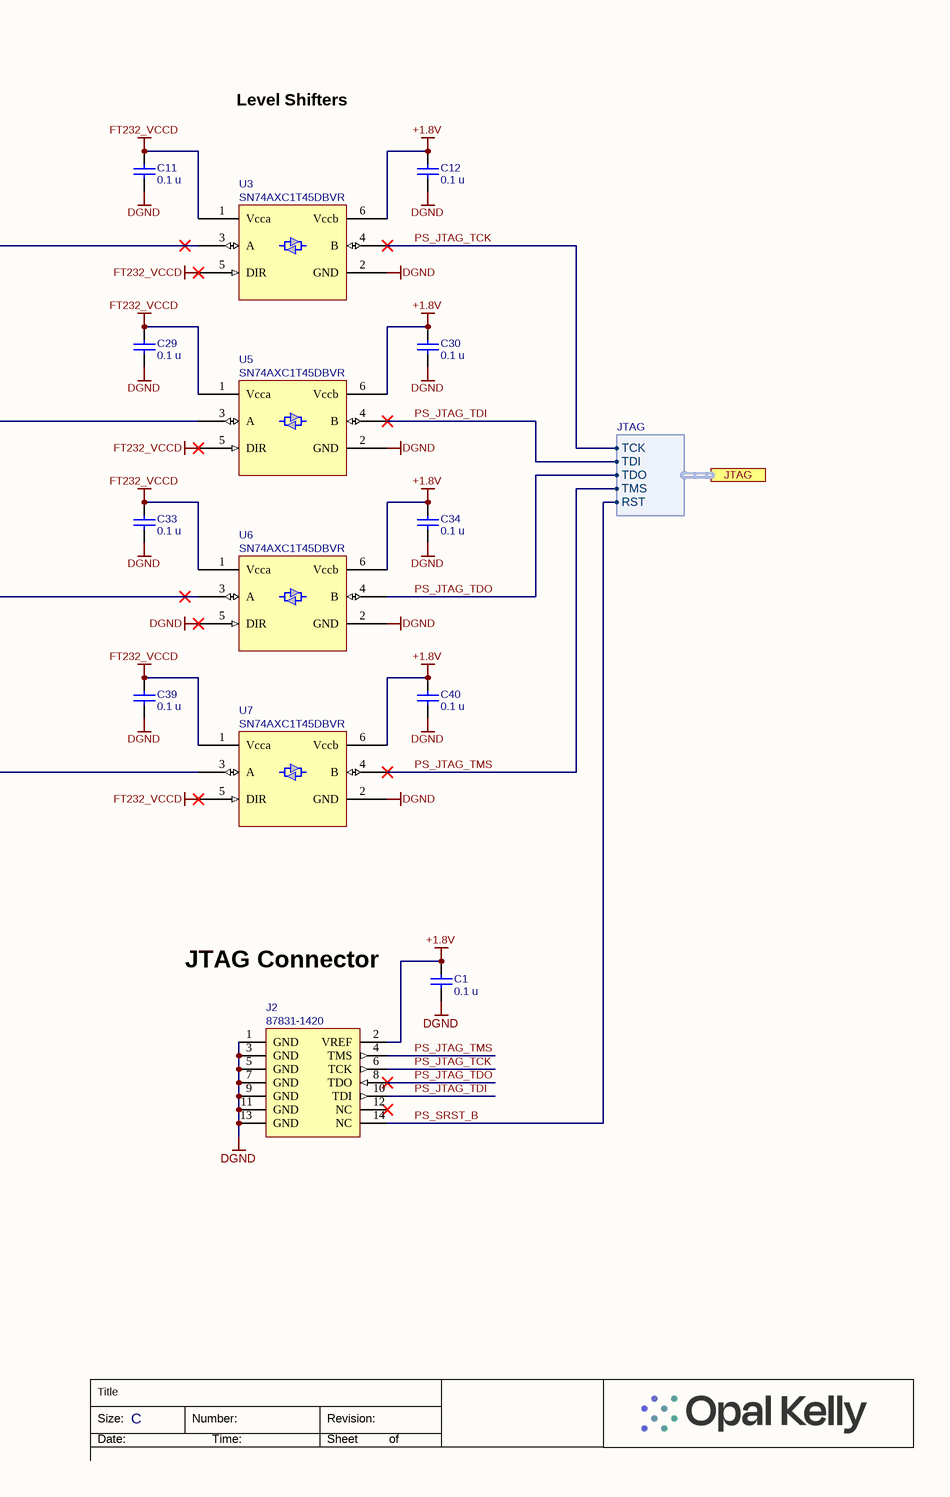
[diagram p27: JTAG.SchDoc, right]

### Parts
C1  value 0.1 u  [CAPC1005X06A]  (hidden comment: SM-0402, 10%, 10v)
C9  value 4.7u  [CAPC1005X06A]  (hidden comment: JMK105BBJ475MV-F)
C10  value 0.1 u  [CAPC1005X06A]  (hidden comment: C0402C104K8PACTU)
C11  value 0.1 u  [CAPC1005X06A]  (hidden comment: C0402C104K8PACTU)
C12  value 0.1 u  [CAPC1005X06A]  (hidden comment: C0402C104K8PACTU)
C13  value 4.7u  [CAPC1005X06A]  (hidden comment: JMK105BBJ475MV-F)
C14  value 0.1 u  [CAPC1005X06A]  (hidden comment: C0402C104K8PACTU)
C15  value 0.1 u  [CAPC1005X06A]  (hidden comment: C0402C104K8PACTU)
C16  value 0.1 u  [CAPC1005X06A]  (hidden comment: C0402C104K8PACTU)
C17  value 0.1 u  [CAPC1005X06A]  (hidden comment: C0402C104K8PACTU)
C18  value 0.01 u  [CAPC1005X06A]  (hidden comment: C0402C103K4RACTU)
C19  value 4.7u  [CAPC1005X06A]  (hidden comment: JMK105BBJ475MV-F)
C22  value 0.1 u  [CAPC1005X06A]  (hidden comment: C0402C104K8PACTU)
C23  value 4.7u  [CAPC1005X06A]  (hidden comment: JMK105BBJ475MV-F)
C28  value 0.1 u  [CAPC1005X06A]  (hidden comment: C0402C104K8PACTU)
C29  value 0.1 u  [CAPC1005X06A]  (hidden comment: C0402C104K8PACTU)
C30  value 0.1 u  [CAPC1005X06A]  (hidden comment: C0402C104K8PACTU)
C31  value 0.1 u  [CAPC1005X06A]  (hidden comment: C0402C104K8PACTU)
C32  value 0.1 u  [CAPC1005X06A]  (hidden comment: C0402C104K8PACTU)
C33  value 0.1 u  [CAPC1005X06A]  (hidden comment: C0402C104K8PACTU)
C34  value 0.1 u  [CAPC1005X06A]  (hidden comment: C0402C104K8PACTU)
C35  value 0.01 u  [CAPC1005X06A]  (hidden comment: C0402C103K4RACTU)
C36  value 0.1 u  [CAPC1005X06A]  (hidden comment: SM-0402, 10%, 10v)
C37  value 18 p  Voltage: 50  [CAPC1005X06A]  (hidden comment: C0402C180J5GACTU)
C38  value 18 p  Voltage: 50  [CAPC1005X06A]  (hidden comment: C0402C180J5GACTU)
C39  value 0.1 u  [CAPC1005X06A]  (hidden comment: C0402C104K8PACTU)
C40  value 0.1 u  [CAPC1005X06A]  (hidden comment: C0402C104K8PACTU)
C41  value 0.1 u  [CAPC1005X06A]  (hidden comment: C0402C104K8PACTU)
C42  value 4.7u  [CAPC1005X06A]  (hidden comment: JMK105BBJ475MV-F)
D5  D5V0FS4U10LP-7  [D5V0FS4U10LP]
FB2  MI0603J601R-10  value 600  [INDC1608X06N]
FB3  MI0603J601R-10  value 600  [INDC1608X06N]
FB4  MI0603J601R-10  value 600  [INDC1608X06N]
FB5  BLM21PG221SN1D  value 220  [RESC2012N]
J2  87831-1420  [XILINX-JTAG]
J21  USB4120-03-C  [USB4120-03-C]
R13  value 5.1 k  [RESC1005X06A]  (hidden comment: CRCW04025K10FKEDC)
R19  value 5.1 k  [RESC1005X06A]  (hidden comment: CRCW04025K10FKEDC)
R20  value 12.0 k  [RESC1005X06A]  (hidden comment: CRCW040212K0FKED)
R21  value 10.0 k  [RESC1005X06A]  (hidden comment: CRCW040210K0FKED)
R22  value 0  [RESC1005X06A]  (hidden comment: CRCW04020000Z0ED)
R23  value 0  [RESC1005X06A]  (hidden comment: CRCW04020000Z0ED)
R24  value 0  [RESC1005X06A]  (hidden comment: CRCW04020000Z0ED)
R25  value 100 k  [RESC1005X06A]  (hidden comment: CRCW0402100KFKED)
R26  value 100 k  [RESC1005X06A]  (hidden comment: CRCW0402100KFKED)
R27  value 2.0 k  [RESC1005X06A]  (hidden comment: CRCW04022K00FKED)
R28  value 10.0 k  [RESC1005X06A]  (hidden comment: CRCW040210K0FKED)
U3  SN74AXC1T45DBVR  [SOT23-6]
U4  FT232HQ  [FT232HQ]
U5  SN74AXC1T45DBVR  [SOT23-6]
U6  SN74AXC1T45DBVR  [SOT23-6]
U7  SN74AXC1T45DBVR  [SOT23-6]
U20  93LC56B-E/MS-CFG001  [MSOP-MS8_N]
Y4  ABM8-12.000MHZ-B2-T  [ABM8]

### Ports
JTAG (harness JTAG)

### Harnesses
JTAG: TDI, TDO, TCK, TMS, RST

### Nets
+1.8V: C1.2 C12.2 C30.2 C34.2 C40.2 J2.2(VREF) U3.6(Vccb) U5.6(Vccb) U6.6(Vccb) U7.6(Vccb)
DGND: C1.1 C9.1 C10.1 C11.1 C12.1 C13.1 C14.1 C15.1 C16.1 C17.1 C18.1 C19.1 C22.1 C23.1 C28.1 C29.1 C30.1 C31.1 C32.1 C33.1 C34.1 C35.1 C36.1 C37.1 C38.1 C39.1 C40.1 C41.1 C42.1 D5.3(A) D5.8(A) FB5.2 J2.1(GND) J2.3(GND) J2.5(GND) J2.7(GND) J2.9(GND) J2.11(GND) J2.13(GND) J21.A1(GND) J21.A12(GND) J21.B1(GND) J21.B12(GND) R13.1 R19.2 R20.1 R22.2 R23.2 R24.2 R26.1 U3.2(GND) U4.4(AGND) U4.9(AGND) U4.10(GND) U4.11(GND) U4.22(GND) U4.23(GND) U4.35(GND) U4.36(GND) U4.41(AGND) U4.42(TEST) U4.47(GND) U4.48(GND) U4.PAD U5.2(GND) U6.2(GND) U6.5(DIR) U7.2(GND) U20.5(VSS) Y4.2(CASE) Y4.4(CASE)
FT232_VCCD: C11.2 C15.2 C16.2 C17.2 C23.2 C28.2 C29.2 C33.2 C39.2 C41.2 C42.2 FB2.1 FB3.1 R21.2 R25.2 R28.2 U3.1(Vcca) U3.5(DIR) U4.12(VCCIO) U4.24(VCCIO) U4.39(VCCD) U4.46(VCCIO) U5.1(Vcca) U5.5(DIR) U6.1(Vcca) U7.1(Vcca) U7.5(DIR) U20.8(VCC)
FT232_VREGIN: C19.2 C22.2 FB4.1 U4.40(VREGIN)
EECLK: R25.1 U4.44(EECLK) U20.2(CLK)
EECS: R26.2 U4.45(EECS) U20.1(CS)
EEDATA: R27.1 U4.43(EEDATA) U20.3(DI)
EEPROM_DO: R27.2 R28.1 U20.4(DO)
FT232_RESET: C35.2 R21.1 U4.34(~{RESET})
FTDI_TCK: U3.3(A) U4.13(ADBUS0_/_TCK_/_SK)
FTDI_TDI: U4.14(ADBUS1_/_TDI_/_DO) U5.3(A)
FTDI_TDO: U4.15(ADBUS2_/_TDO_/_DI) U6.3(A)
FTDI_TMS: U4.16(ADBUS3_/_TMS_/_CS) U7.3(A)
PS_JTAG_TCK: J2.6(TCK) U3.4(B) ; port JTAG.TCK
PS_JTAG_TDI: J2.10(TDI) U5.4(B) ; port JTAG.TDI
PS_JTAG_TDO: J2.8(TDO) U6.4(B) ; port JTAG.TDO
PS_JTAG_TMS: J2.4(TMS) U7.4(B) ; port JTAG.TMS
PS_SRST_B: J2.14(NC) ; port JTAG.RST
USB_JTAG_DN: D5.5,6(K) J21.A7(DN1) J21.B7(DN2) U4.6(DM)
USB_JTAG_DP: D5.4,7(K) J21.A6(DP1) J21.B6(DP2) U4.7(DP)
VBUS_C: C18.2 D5.2,9(K) FB4.2 J21.A4(VBUS) J21.A9(VBUS) J21.B4(VBUS) J21.B9(VBUS)
VCCA: C32.2 U4.37(VCCA)
VCORE: C31.2 U4.38(VCORE)
NetC9_2: C9.2 C10.2 FB2.2 U4.8(VPLL)
NetC13_2: C13.2 C14.2 FB3.2 U4.3(VPHY)
NetC36_2: C36.2 FB5.1 J21.M1(SHELL) J21.M2(SHELL) J21.M3(SHELL) J21.M4(SHELL) R22.1 R23.1 R24.1
NetC37_2: C37.2 U4.1(OSCI) Y4.1(OSC1)
NetC38_2: C38.2 U4.2(OSCO) Y4.3(OSC2)
NetJ21_A5: J21.A5(CC1) R13.2
NetJ21_B5: J21.B5(CC2) R19.1
NetR20_2: R20.2 U4.5(REF)

Not connected (* = marked no-connect by the designer): D5 1,10(K)*; J2 12(NC)*; J21 A8(SBU1)* B8(SBU2)*; U4 17(ADBUS4_/_GPIOL0)* 18(ADBUS5_/_GPIOL1)* 19(ADBUS6_/_GPIOL2)* 20(ADBUS7_/_GPIOL3)* 21(ACBUS0_/_GPIOH0)* 25(ACBUS1_/_GPIOH1)* 26(ACBUS2_/_GPIOH2)* 27(ACBUS3_/_GPIOH3)* 28(ACBUS4_/_GPIOH4)* 29(ACBUS5_/_GPIOH5)* 30(ACBUS6_/_GPIOH6)* 31(ACBUS7_/_GPIOH7)* 32(ACBUS8)* 33(ACBUS9)*; U20 6(NC)* 7(NC)*

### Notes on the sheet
- (near C10) USB JTAG
- Level Shifters
- JTAG
- USB Type C Connector
- EEPROM
- JTAG Connector
- Title
- Size:
- Date:
- C
- Number:
- Time:
- Revision:
- Sheet
- of

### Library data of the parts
C1 C36 = 000070: as C170 on sheet DisplayPort-Source
C9 C13 C19 C23 = 000824: Ceramic capacitor; Manufacturer: Taiyo Yuden; partnumber: 000824; Description 2: 0402, 6.3V; ValueFloat: 4.7E-6; Tolerance (%): 20; x_lifecycle_status: Production
C10-C12 C14-C17 C22 C28-C34 C39-C41 = 000070: as C3-C8 on sheet Clocks
C18 C35 = 000295: as C100 on sheet Ethernet
C37 C38 = 001640: Ceramic capacitor; Partnumber: 001640; Manufacturer: Kemet; ValueFloat: 1.8E-11; Tolerance (%): 5; Description 2: SM-0402, 5%, 50v, C0G
C42 = 000824: Partnumber: 000824; manufacturer: Taiyo Yuden; ValueFloat: 4.7E-6; x_tolerance: 20
D5 = 002405: 4 channel TVS diode array; Manufacturer: Diodes Incorporated; PartNumber: 002405; Class I: Discrete; Class II: Diode - Zener; Description 2: USB, TVS
FB2-FB4 = 000569: Ferrite bead; Partnumber: 000569; Manufacturer: Steward; Description 2: SM-0603, 1 A, 600 ohm at 100 MHz
FB5 = 000783: Ferrite Chip; Manufacturer: Murata; partnumber: 000783; Description 2: 220 OHM 2000MA 0805
J2 = 000541: 2mm header, shrouded; Manufacturer: Molex; partnumber: 000541; Description 2: Dual-row, 14-pos, Xilinx JTAG compatible
J21 = 002404: USB 2.0 Type-C receptacle vertical-mount; Partnumber: 002404; Manufacturer: GCT; Description 2: Surface-mount, Vertical-mount
R13 R19 = 001919: Thick-film resistor; Partnumber: 001919; Manufacturer: Vishay; ValueFloat: 5100; Tolerance (%): 1; Description 2: SM-0402, 1%, 1/16W
R20 = 000826: Thick-film resistor; Partnumber: 000826; Manufacturer: Vishay; ValueFloat: 12000; Tolerance (%): 1; Description 2: SM-0402, 1%, 1/16W
R21 R28 = 001521: as R103 on sheet Ethernet
R22-R24 = 000755: as R93 on sheet Ethernet
R25 R26 = 001070: Thick-film resistor; Partnumber: 001070; Manufacturer: Vishay; ValueFloat: 100000; Tolerance (%): 1; Description 2: SM-0402, 1%, 1/16W
R27 = 001162: Thick-film resistor; Partnumber: 001162; Manufacturer: Vishay; ValueFloat: 2000; Tolerance (%): 1; Description 2: SM-0402, 1%, 1/16W
U3 U5-U7 = 002400: Level Translator, 0.65V - 3.6V, Direction Control; Partnumber: 002400; Manufacturer: Texas Instruments; Description 2: Single Bit, Dual Supplies, SOT23-6
U4 = 002398: Partnumber: 002398; manufacturer: FTDI
U20 = 002441: Partnumber: 002441; manufacturer: Opal Kelly Incorporated
Y4 = 002402: Crystal; Partnumber: 002402; Manufacturer: Abracon; Description 2: 12.0 MHz, +/- 50ppm, 3.2mm x 2.5mm, 18 pF

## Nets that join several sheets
+1.1V_ETH: Power (6 pins), Ethernet (12 pins)
+1.8V: Top (TP1.1), USB (9 pins), Expansion-MC1 (J4.18), Expansion-MC2 (MC2.1 MC2.3), Ethernet (26 pins), JTAG (10 pins)
+2.5V_ETH: Power (6 pins), Ethernet (6 pins)
+3.3V: Top (TP3.1), Expansion-MC3 (MC3.166 MC3.168), Clocks (12 pins)
+3.3V_AUX: USB (8 pins), Expansion-MC1 (6 pins), Expansion-MC2 (J5.40 J6.40 J7.40), Expansion-MC3 (6 pins), Power (14 pins), Ethernet (7 pins), DisplayPort-Source (6 pins)
+3.3V_QSFP: QSFP (31 pins), Power (7 pins)
+5V_AUX: USB (8 pins), Power (7 pins)
+5V_SZG: Expansion-MC1 (J1.2), Expansion-MC2 (J5.2 J6.2 J7.2), Expansion-MC3 (J8.2 J9.2 J11.2), Power (7 pins)
+VDCIN: Expansion-MC3 (12 pins), Power (17 pins)
DGND: Top (TP2.1 TP5.1 TP8.1 TP11.1), USB (35 pins), QSFP (61 pins), Expansion-MC1 (39 pins), Expansion-MC2 (10 pins), Expansion-MC3 (19 pins), Power (65 pins), Ethernet (53 pins), Clocks (12 pins), DisplayPort-Source (18 pins), JTAG (71 pins)
VCCO_28: Top (TP6.1), Expansion-MC1 (J1.39), Expansion-MC2 (J7.39), Expansion-MC3 (MC3.158)
VCCO_67: Top (TP12.1), Expansion-MC2 (J6.39), Expansion-MC3 (C219.2 J11.39 MC3.103 U34.6)
VCCO_68: Top (TP7.1), Expansion-MC2 (J5.39), Expansion-MC3 (J9.39 MC3.51)
VCCO_87_88: Top (TP13.1), QSFP (15 pins), Expansion-MC3 (J8.39 MC3.25)
VREF_28: Top (TP9.1), Expansion-MC3 (MC3.162)
VREF_67: Top (TP4.1), Expansion-MC3 (MC3.94)
VREF_68: Top (TP10.1), Expansion-MC3 (MC3.50)
CLK0A: Expansion-MC2 (MC2.10), Clocks (TP28.1 U2.22)
CLK0B: Expansion-MC2 (MC2.12), Clocks (TP24.1 U2.21)
CLK1A: Expansion-MC2 (MC2.30), Clocks (TP29.1 U2.18)
CLK1B: Expansion-MC2 (MC2.32), Clocks (TP25.1 U2.17)
CLK2A: Expansion-MC2 (MC2.66), Clocks (TP30.1 U2.14)
CLK2B: Expansion-MC2 (MC2.68), Clocks (TP26.1 U2.13)
CLK3A: Expansion-MC2 (MC2.29), Clocks (TP31.1 U2.10)
CLK3B: Expansion-MC2 (MC2.31), Clocks (TP27.1 U2.9)
DISPLAYPORT_PS_SRC_AUX_N_C: Expansion-MC3 (MC3.153), DisplayPort-Source (C171.2 R158.1)
DISPLAYPORT_PS_SRC_AUX_P_C: Expansion-MC3 (MC3.151), DisplayPort-Source (C170.2 R153.2)
DISPLAYPORT_PS_SRC_HPD_3V3: Expansion-MC3 (U34.3), DisplayPort-Source (R159.2 R181.1)
DISPLAYPORT_PS_SRC_LANE0_N: Expansion-MC2 (MC2.24), DisplayPort-Source (C185.2)
DISPLAYPORT_PS_SRC_LANE0_P: Expansion-MC2 (MC2.22), DisplayPort-Source (C182.2)
DISPLAYPORT_PS_SRC_LANE1_N: Expansion-MC2 (MC2.28), DisplayPort-Source (C189.2)
DISPLAYPORT_PS_SRC_LANE1_P: Expansion-MC2 (MC2.26), DisplayPort-Source (C187.2)
GIGE_INT_B: Expansion-MC1 (MC1.91), Ethernet (R114.1 U18.60)
GIGE_LED_MODE: Expansion-MC1 (MC1.94), Ethernet (R183.1 R184.2)
GIGE_MDC: Expansion-MC1 (MC1.102), Ethernet (R116.1 U18.20)
GIGE_MDIO: Expansion-MC1 (MC1.100), Ethernet (R115.1 U18.21)
GIGE_RESET_B: Expansion-MC1 (MC1.92), Ethernet (D3.2 R119.1)
GIGE_RX_CLK: Expansion-MC1 (MC1.64), Ethernet (U18.43)
GIGE_RX_DV: Expansion-MC1 (MC1.67), Ethernet (R95.1 R96.2 U18.53)
GIGE_RXD0: Expansion-MC1 (MC1.68), Ethernet (R62.1 R90.2 U18.44)
GIGE_RXD1: Expansion-MC1 (MC1.65), Ethernet (U18.45)
GIGE_RXD2: Expansion-MC1 (MC1.69), Ethernet (R63.1 R91.2 U18.46)
GIGE_RXD3: Expansion-MC1 (MC1.70), Ethernet (U18.47)
GIGE_TX_CLK: Expansion-MC1 (MC1.71), Ethernet (U18.40)
GIGE_TX_EN: Expansion-MC1 (MC1.66), Ethernet (U18.52)
GIGE_TXD0: Expansion-MC1 (MC1.72), Ethernet (U18.38)
GIGE_TXD1: Expansion-MC1 (MC1.62), Ethernet (U18.37)
GIGE_TXD2: Expansion-MC1 (MC1.61), Ethernet (U18.36)
GIGE_TXD3: Expansion-MC1 (MC1.63), Ethernet (U18.35)
NetMC3_48: QSFP (R10.1 R11.2), Expansion-MC3 (MC3.48)
PS_I2C0_SCL_3V3: USB (U14.26), Expansion-MC1 (J1.1 J13.3 MC1.58 U1.6), Expansion-MC2 (J5.1 J6.1 J7.1), Expansion-MC3 (J8.1 J9.1 J11.1), Power (U19.43), Ethernet (U15.6), Clocks (U2.12)
PS_I2C0_SDA_3V3: USB (U14.25), Expansion-MC1 (J1.3 J13.2 MC1.60 U1.5), Expansion-MC2 (J5.3 J6.3 J7.3), Expansion-MC3 (J8.3 J9.3 J11.3), Power (U19.42), Ethernet (U15.5), Clocks (U2.19)
PS_JTAG_TCK: Expansion-MC1 (MC1.59), JTAG (J2.6 U3.4)
PS_JTAG_TDI: Expansion-MC1 (MC1.53), JTAG (J2.10 U5.4)
PS_JTAG_TDO: Expansion-MC1 (MC1.55), JTAG (J2.8 U6.4)
PS_JTAG_TMS: Expansion-MC1 (MC1.57), JTAG (J2.4 U7.4)
PS_SRST_B: Expansion-MC1 (J4.7 MC1.113), JTAG (J2.14)
QSFP1_INT_B: QSFP (U8.3), Expansion-MC3 (MC3.42)
QSFP1_LP_MODE: QSFP (U9.5), Expansion-MC3 (MC3.36)
QSFP1_MODPRS_B: QSFP (U9.2), Expansion-MC3 (MC3.40)
QSFP1_MODSEL_B: QSFP (U9.4), Expansion-MC3 (MC3.38)
QSFP1_RESET_B: QSFP (U9.3), Expansion-MC3 (MC3.34)
QSFP1_RX1N: QSFP (J14.18), Expansion-MC2 (MC2.47)
QSFP1_RX1P: QSFP (J14.17), Expansion-MC2 (MC2.45)
QSFP1_RX2N: QSFP (J14.21), Expansion-MC2 (MC2.43)
QSFP1_RX2P: QSFP (J14.22), Expansion-MC2 (MC2.41)
QSFP1_RX3N: QSFP (J14.15), Expansion-MC2 (MC2.39)
QSFP1_RX3P: QSFP (J14.14), Expansion-MC2 (MC2.37)
QSFP1_RX4N: QSFP (J14.24), Expansion-MC2 (MC2.35)
QSFP1_RX4P: QSFP (J14.25), Expansion-MC2 (MC2.33)
QSFP1_SCL: QSFP (R48.1 U10.4), Expansion-MC3 (MC3.44)
QSFP1_SDA: QSFP (R47.1 U10.5), Expansion-MC3 (MC3.46)
QSFP1_TX1N: QSFP (J14.37), Expansion-MC2 (MC2.48)
QSFP1_TX1P: QSFP (J14.36), Expansion-MC2 (MC2.46)
QSFP1_TX2N: QSFP (J14.2), Expansion-MC2 (MC2.44)
QSFP1_TX2P: QSFP (J14.3), Expansion-MC2 (MC2.42)
QSFP1_TX3N: QSFP (J14.34), Expansion-MC2 (MC2.40)
QSFP1_TX3P: QSFP (J14.33), Expansion-MC2 (MC2.38)
QSFP1_TX4N: QSFP (J14.5), Expansion-MC2 (MC2.36)
QSFP1_TX4P: QSFP (J14.6), Expansion-MC2 (MC2.34)
QSFP2_INT_B: QSFP (U11.3), Expansion-MC3 (MC3.45)
QSFP2_LP_MODE: QSFP (U23.5), Expansion-MC3 (MC3.37)
QSFP2_MODPRS_B: QSFP (U23.2), Expansion-MC3 (MC3.41)
QSFP2_MODSEL_B: QSFP (U23.4), Expansion-MC3 (MC3.39)
QSFP2_RESET_B: QSFP (U23.3), Expansion-MC3 (MC3.35)
QSFP2_RX1N: QSFP (J15.18), Expansion-MC2 (MC2.63)
QSFP2_RX1P: QSFP (J15.17), Expansion-MC2 (MC2.61)
QSFP2_RX2N: QSFP (J15.21), Expansion-MC2 (MC2.59)
QSFP2_RX2P: QSFP (J15.22), Expansion-MC2 (MC2.57)
QSFP2_RX3N: QSFP (J15.15), Expansion-MC2 (MC2.55)
QSFP2_RX3P: QSFP (J15.14), Expansion-MC2 (MC2.53)
QSFP2_RX4N: QSFP (J15.24), Expansion-MC2 (MC2.51)
QSFP2_RX4P: QSFP (J15.25), Expansion-MC2 (MC2.49)
QSFP2_SCL: QSFP (R50.1 U10.2), Expansion-MC3 (MC3.47)
QSFP2_SDA: QSFP (R49.1 U10.3), Expansion-MC3 (MC3.43)
QSFP2_TX1N: QSFP (J15.37), Expansion-MC2 (MC2.64)
QSFP2_TX1P: QSFP (J15.36), Expansion-MC2 (MC2.62)
QSFP2_TX2N: QSFP (J15.2), Expansion-MC2 (MC2.60)
QSFP2_TX2P: QSFP (J15.3), Expansion-MC2 (MC2.58)
QSFP2_TX3N: QSFP (J15.34), Expansion-MC2 (MC2.56)
QSFP2_TX3P: QSFP (J15.33), Expansion-MC2 (MC2.54)
QSFP2_TX4N: QSFP (J15.5), Expansion-MC2 (MC2.52)
QSFP2_TX4P: QSFP (J15.6), Expansion-MC2 (MC2.50)
SZG_PORTE_C2P_CLKN: Expansion-MC2 (J6.36), Expansion-MC3 (MC3.150)
SZG_PORTE_C2P_CLKP: Expansion-MC2 (J6.34), Expansion-MC3 (MC3.148)
SZG_PORTE_P2C_CLKN: Expansion-MC2 (J6.35), Expansion-MC3 (MC3.145)
SZG_PORTE_P2C_CLKP: Expansion-MC2 (J6.33), Expansion-MC3 (MC3.143)
SZG_PORTE_S0: Expansion-MC2 (J6.14), Expansion-MC3 (MC3.141)
SZG_PORTE_S1: Expansion-MC2 (J6.16), Expansion-MC3 (MC3.152)
SZG_PORTE_S2: Expansion-MC2 (J6.17), Expansion-MC3 (MC3.154)
SZG_PORTE_S3: Expansion-MC2 (J6.18), Expansion-MC3 (MC3.147)
SZG_PORTE_S4: Expansion-MC2 (J6.19), Expansion-MC3 (MC3.149)
SZG_PORTE_S5: Expansion-MC2 (J6.20), Expansion-MC3 (MC3.138)
SZG_PORTE_S6: Expansion-MC2 (J6.21), Expansion-MC3 (MC3.140)
SZG_PORTE_S7: Expansion-MC2 (J6.22), Expansion-MC3 (MC3.142)
SZG_PORTE_S8: Expansion-MC2 (J6.23), Expansion-MC3 (MC3.144)
SZG_PORTE_S9: Expansion-MC2 (J6.24), Expansion-MC3 (MC3.146)
SZG_PORTF_C2P_CLKN: Expansion-MC1 (MC1.46), Expansion-MC2 (J7.36)
SZG_PORTF_C2P_CLKP: Expansion-MC1 (MC1.44), Expansion-MC2 (J7.34)
SZG_PORTF_P2C_CLKN: Expansion-MC1 (MC1.36), Expansion-MC2 (J7.35)
SZG_PORTF_P2C_CLKP: Expansion-MC1 (MC1.34), Expansion-MC2 (J7.33)
SZG_PORTF_S0: Expansion-MC1 (MC1.35), Expansion-MC2 (J7.14)
SZG_PORTF_S1: Expansion-MC1 (MC1.37), Expansion-MC2 (J7.16)
SZG_PORTF_S2: Expansion-MC1 (MC1.39), Expansion-MC2 (J7.17)
SZG_PORTF_S3: Expansion-MC1 (MC1.41), Expansion-MC2 (J7.18)
SZG_PORTF_S4: Expansion-MC1 (MC1.43), Expansion-MC2 (J7.19)
SZG_PORTF_S5: Expansion-MC1 (MC1.45), Expansion-MC2 (J7.20)
SZG_PORTF_S6: Expansion-MC1 (MC1.47), Expansion-MC2 (J7.21)
SZG_PORTF_S7: Expansion-MC1 (MC1.38), Expansion-MC2 (J7.22)
SZG_PORTF_S8: Expansion-MC1 (MC1.40), Expansion-MC2 (J7.23)
SZG_PORTF_S9: Expansion-MC1 (MC1.42), Expansion-MC2 (J7.24)
SZG_PORTG_C2P_CLKN: Expansion-MC2 (J5.36), Expansion-MC3 (MC3.99)
SZG_PORTG_C2P_CLKP: Expansion-MC2 (J5.34), Expansion-MC3 (MC3.97)
SZG_PORTG_P2C_CLKN: Expansion-MC2 (J5.35), Expansion-MC3 (MC3.102)
SZG_PORTG_P2C_CLKP: Expansion-MC2 (J5.33), Expansion-MC3 (MC3.100)
SZG_PORTG_S0: Expansion-MC2 (J5.14), Expansion-MC3 (MC3.90)
SZG_PORTG_S1: Expansion-MC2 (J5.16), Expansion-MC3 (MC3.92)
SZG_PORTG_S2: Expansion-MC2 (J5.17), Expansion-MC3 (MC3.82)
SZG_PORTG_S3: Expansion-MC2 (J5.18), Expansion-MC3 (MC3.96)
SZG_PORTG_S4: Expansion-MC2 (J5.19), Expansion-MC3 (MC3.86)
SZG_PORTG_S5: Expansion-MC2 (J5.20), Expansion-MC3 (MC3.98)
SZG_PORTG_S6: Expansion-MC2 (J5.21), Expansion-MC3 (MC3.84)
SZG_PORTG_S7: Expansion-MC2 (J5.22), Expansion-MC3 (MC3.106)
SZG_PORTG_S8: Expansion-MC2 (J5.23), Expansion-MC3 (MC3.88)
SZG_PORTG_S9: Expansion-MC2 (J5.24), Expansion-MC3 (MC3.104)
USB_CLKOUT: USB (U13.1), Expansion-MC1 (MC1.93)
USB_DATA0: USB (U13.3), Expansion-MC1 (MC1.105)
USB_DATA1: USB (U13.4), Expansion-MC1 (MC1.108)
USB_DATA2: USB (U13.5), Expansion-MC1 (MC1.97)
USB_DATA3: USB (U13.6), Expansion-MC1 (MC1.103)
USB_DATA4: USB (U13.7), Expansion-MC1 (MC1.101)
USB_DATA5: USB (U13.9), Expansion-MC1 (MC1.104)
USB_DATA6: USB (U13.10), Expansion-MC1 (MC1.98)
USB_DATA7: USB (U13.13), Expansion-MC1 (MC1.106)
USB_DIR: USB (U13.31), Expansion-MC1 (MC1.95)
USB_NXT: USB (U13.2), Expansion-MC1 (MC1.107)
USB_RESET_B: USB (U13.27), Expansion-MC1 (MC1.96)
USB_SSRX_N: USB (U14.10), Expansion-MC2 (MC2.15)
USB_SSRX_P: USB (U14.9), Expansion-MC2 (MC2.13)
USB_SSTX_N: USB (U14.7), Expansion-MC2 (MC2.16)
USB_SSTX_P: USB (U14.6), Expansion-MC2 (MC2.14)
USB_STP: USB (U13.29), Expansion-MC1 (MC1.99)
USB_TYPEC_INT_B: USB (R80.1 U14.23), Expansion-MC1 (MC1.74)

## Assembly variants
DEFAULT: not fitted C154 C164 C215 D2 D3 J2 J3 J10 J13 R2 R3 R7 R10 R11 R62 R63 R64 R70 R73 R83 R87 R88 R89 R92 R93 R104 R105 R107 R108 R116 R117 R121 R140 R152 R153 R158 R168 R169 R184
